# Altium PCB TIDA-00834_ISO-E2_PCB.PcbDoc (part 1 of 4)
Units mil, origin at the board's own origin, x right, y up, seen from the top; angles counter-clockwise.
Board outline 9055.12 x 4133.86 mil, 4 copper layers (Top Layer, GND, PWR, Bottom Layer), stack 61.92 mil thick; 647 components, 282 nets, 1430 pads, 409 vias.
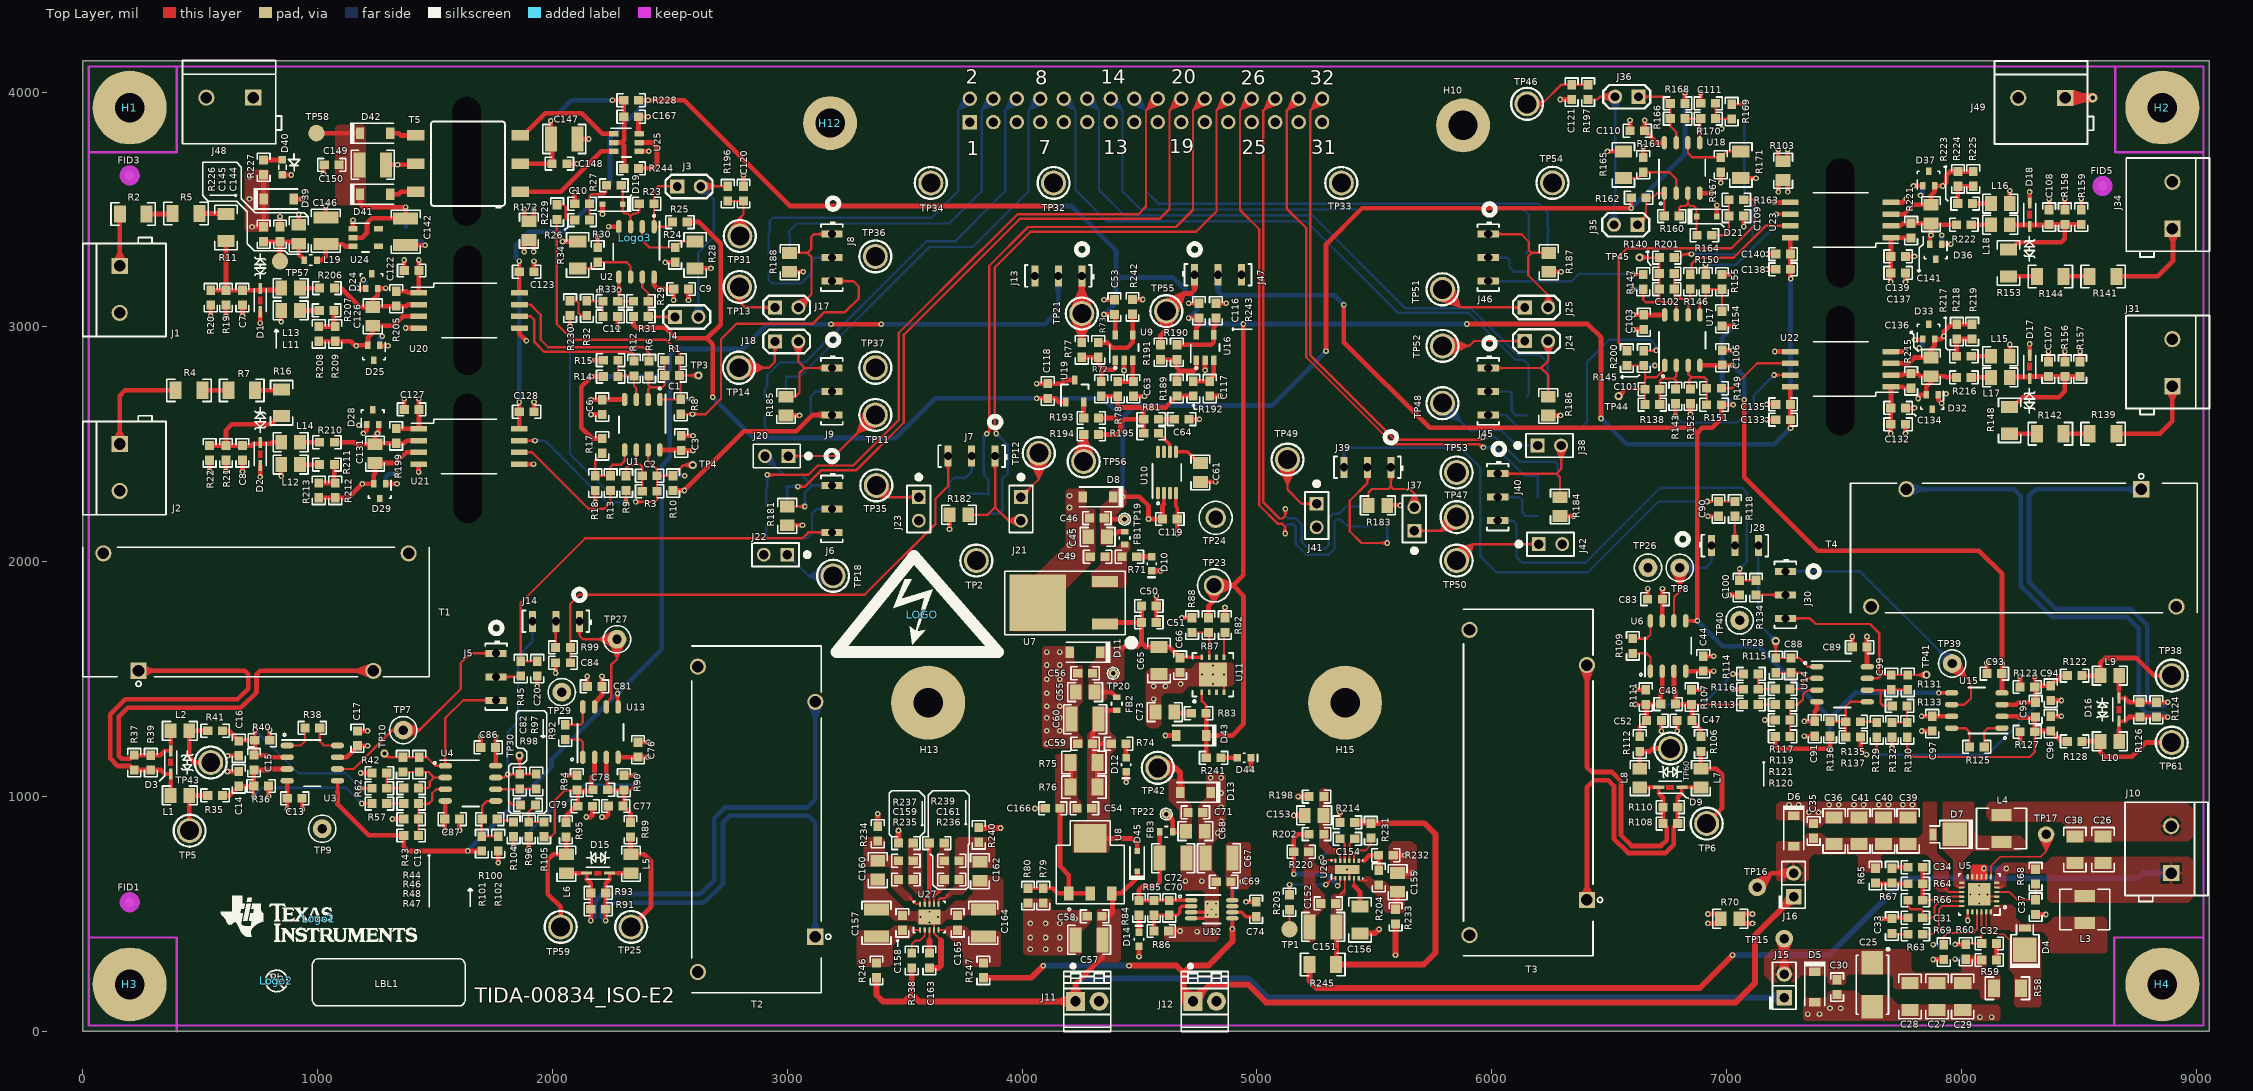
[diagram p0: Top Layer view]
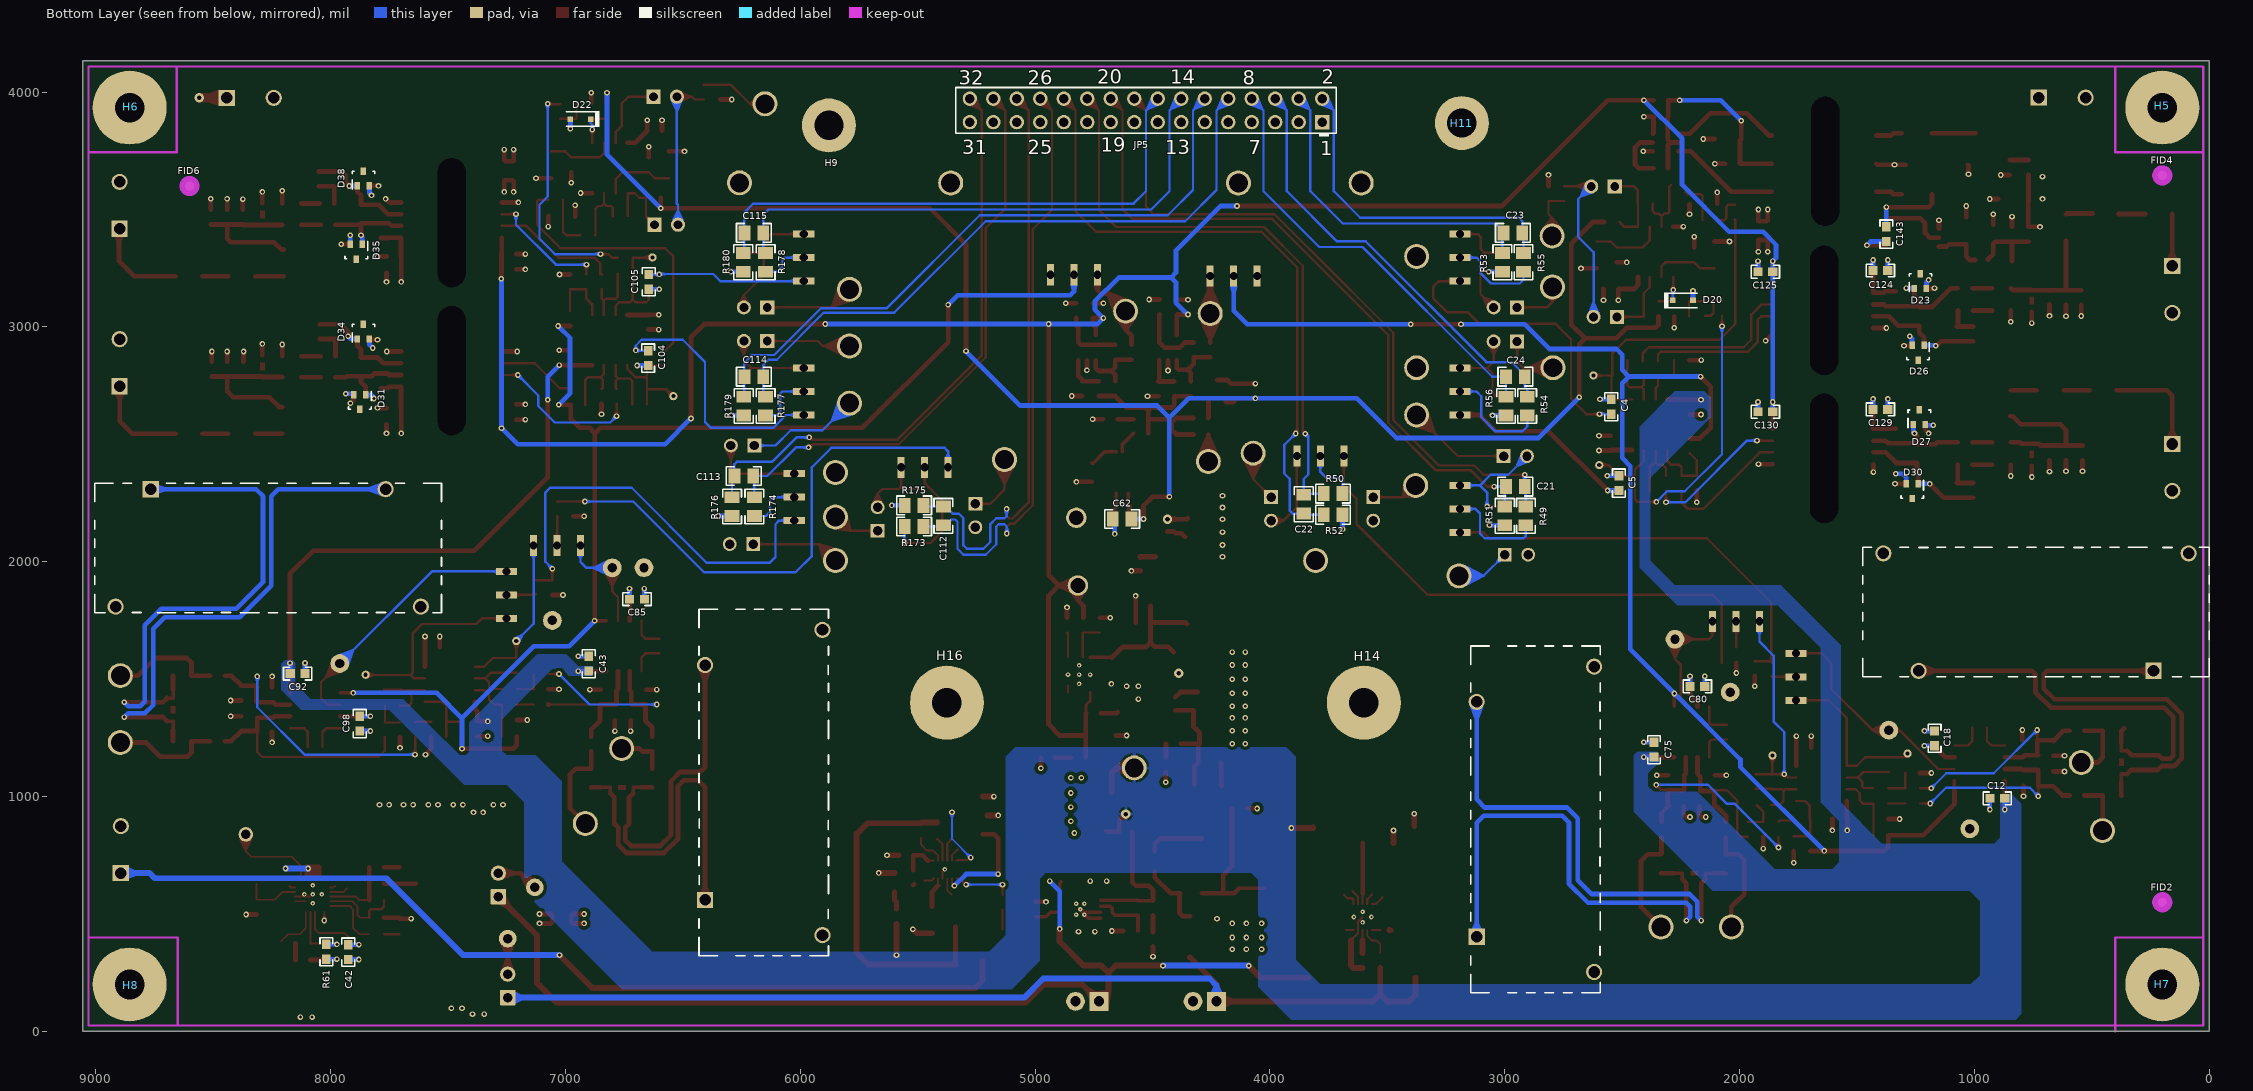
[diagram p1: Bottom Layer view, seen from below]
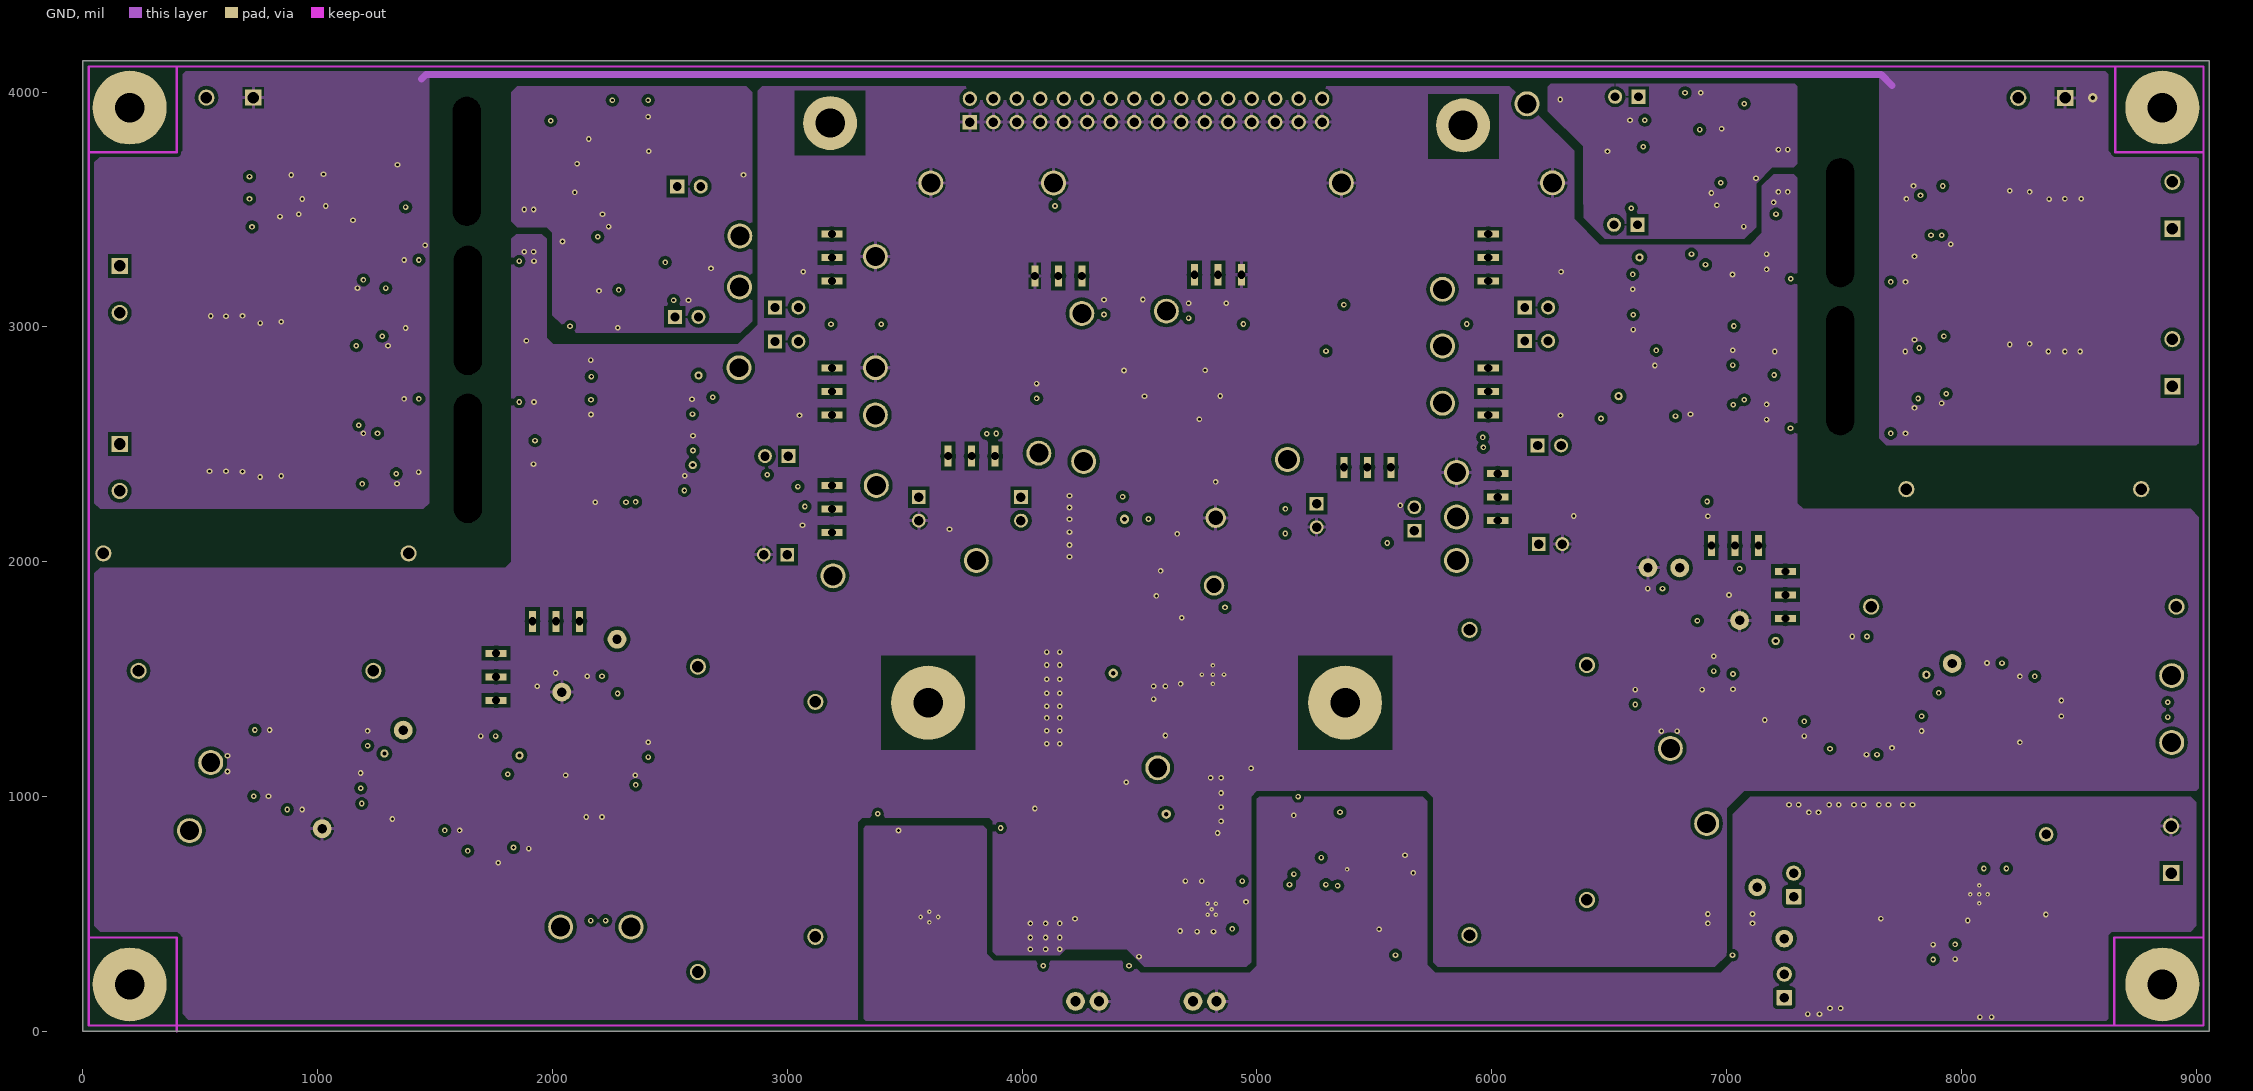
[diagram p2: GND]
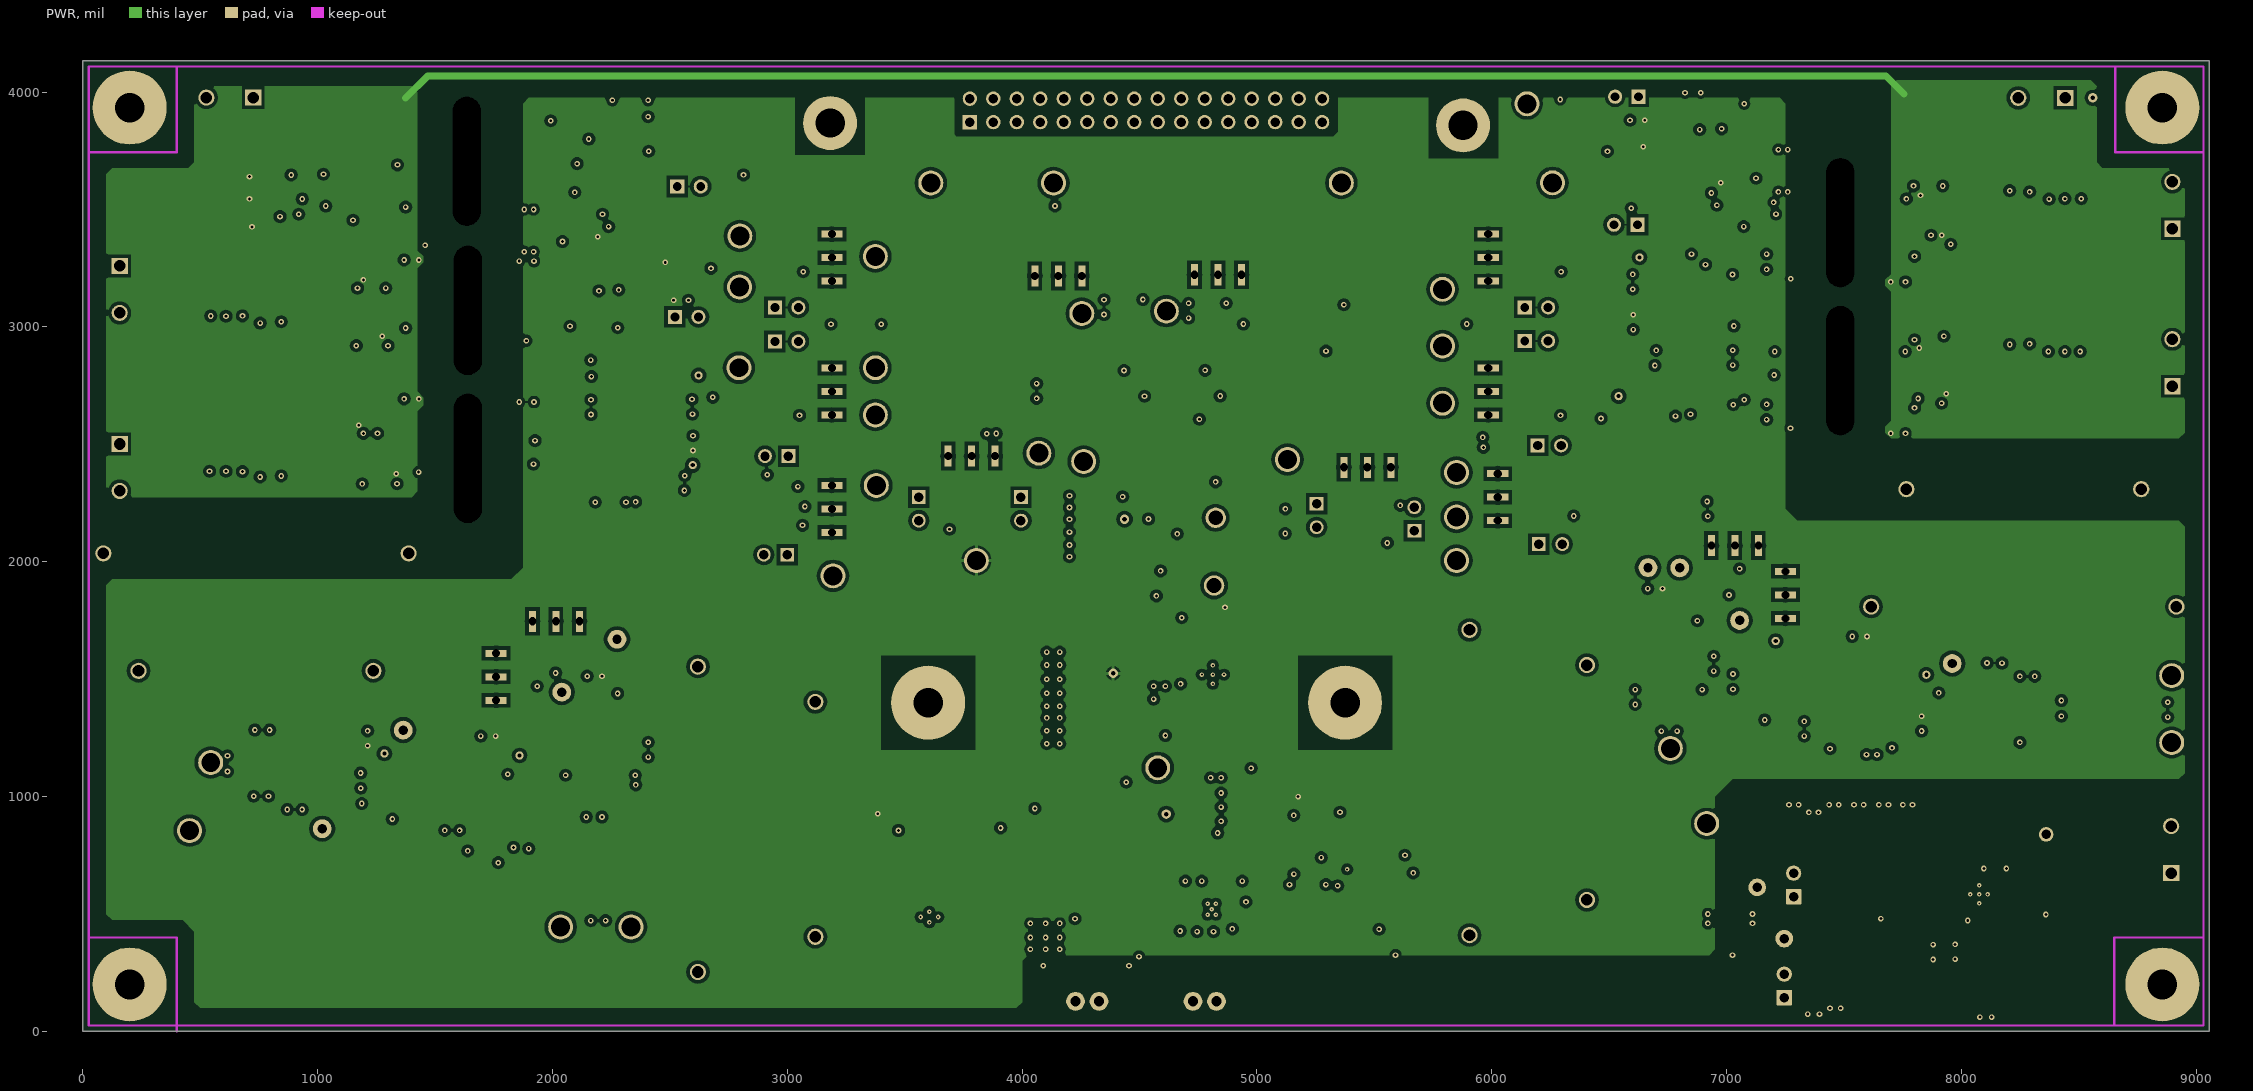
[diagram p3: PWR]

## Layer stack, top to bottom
Top Solder: solder mask 0.4, Solder Resist, Dk 4.3
Top Layer: signal copper 1.38
Dielectric1: prepreg 6.7, FR-4 High Tg, Dk 4.3
GND: signal copper 1.38
Dielectric 2: core 43, FR-4 High Tg, Dk 4.3
PWR: signal copper 1.38
Dielectric 3: prepreg 6.7, FR-4 High Tg, Dk 4.3
Bottom Layer: signal copper 1.38
Bottom Solder: solder mask 0.4, Solder Resist, Dk 4.3

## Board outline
0,0 0,4133.86 9055.12,4133.86 9055.12,0

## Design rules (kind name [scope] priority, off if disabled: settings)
AcuteAngle [All] p1: minimum=4.50000000000000E+0001 checktracksonly=FALSE
AssemblyTestPointUsage [All] p1: valid=2
Clearance Clearance_Keepouts [((IsTrack Or IsArc) And Not InPoly) And IsFree and IsKeepOut vs ((IsTrack Or IsArc) And Not InPoly) And IsFree and IsKeepOut] p1: gap=0
Clearance Clearance_Poly [InPolygon] p2: gap=25 except(8: SMDPad-Poly; 15: Track-Poly THPad-Poly Via-Poly; 20: Poly-Poly)
Clearance [All] p3: gap=7.87
ComponentClearance ComponentClearance_MountingHoles_FiducialMarks [InComponentClass('Mounting Holes') vs InComponentClass('FiducialMark')] p1: gap=50 collisioncheckmode=3 verticalgap=10 showdistances=FALSE
ComponentClearance ComponentClearance_Shunt [InComponentClass('Header') vs InComponentClass('Shunt')] p2: gap=0 collisioncheckmode=3 verticalgap=0 showdistances=FALSE
ComponentClearance ComponentClearance_Logo [InComponentClass('Logo')] p3: gap=50 collisioncheckmode=3 verticalgap=10 showdistances=FALSE
ComponentClearance ComponentClearance_ScrewToNut [(HasFootprint('NY PMS 440 0025 PH')) vs (HasFootprint('Keystone_1902C'))] p4: gap=5 collisioncheckmode=3 verticalgap=10 showdistances=FALSE
ComponentClearance ComponentClearance_MountingHoles [InComponentClass('Mounting Holes')] p5: gap=150 collisioncheckmode=3 verticalgap=100000 showdistances=FALSE
ComponentClearance ComponentClearance_SmallPassives [HasFootprint('0201*') or HasFootprint('0402*') or HasFootprint('0508') or HasFootprint('0603*') or HasFootprint('0612') or HasFootprint('0805*') or HasFootprint('0815*') or HasFootprint('0830*') or HasFootprint('1206*') or HasFootprint('1210*') or HasFootprint('1808*') or HasFootprint('1812*') or HasFootprint('1825*') or HasFootprint('2010*') or HasFootprint('2220*') or HasFootprint('2225*') or HasFootprint('2512*') or HasFootprint('2728*') or HasFootprint('3518*') vs HasFootprint('0201*') or HasFootprint('0402*') or HasFootprint('0508') or HasFootprint('0603*') or HasFootprint('0612') or HasFootprint('0805*') or HasFootprint('0815*') or HasFootprint('0830*') or HasFootprint('1206*') or HasFootprint('1210*') or HasFootprint('1808*') or HasFootprint('1812*') or HasFootprint('1825*') or HasFootprint('2010*') or HasFootprint('2220*') or HasFootprint('2225*') or HasFootprint('2512*') or HasFootprint('2728*') or HasFootprint('3518*')] p6: gap=14.96 collisioncheckmode=3 verticalgap=10 showdistances=FALSE
ComponentClearance ComponentClearance_THtoSMT [IsThruComponent vs IsSMTComponent] p7: gap=40 collisioncheckmode=3 verticalgap=30 showdistances=FALSE
ComponentClearance ComponentClearance_THtoTH [IsThruComponent vs IsThruComponent] p8: gap=30 collisioncheckmode=3 verticalgap=30 showdistances=FALSE
ComponentClearance [All] p9: gap=30 collisioncheckmode=3 verticalgap=10 showdistances=FALSE
DiffPairsRouting [All] p1: maxlimit=100 minlimit=10 mostfreqgap=10 toplayer_minwidth=15 toplayer_maxwidth=15 toplayer_prefwidth=15 midlayer1_minwidth=15 midlayer1_maxwidth=15 midlayer1_prefwidth=15 midlayer2_minwidth=15 midlayer2_maxwidth=15 midlayer2_prefwidth=15 bottomlayer_minwidth=15 bottomlayer_maxwidth=15 bottomlayer_prefwidth=15 maxuncoupledlength=1000
FabricationTestPointUsage TestPointUsage [All] p1: valid=2 allowmultiple=FALSE
FabricationTestpoint Testpoint [All] p1: side=3 testpointundercomponent=TRUE minsize=40 maxsize=100 preferedsize=60 minholesize=0 maxholesize=40 preferedholesize=32 testpointgrid=1 allowsidetop=TRUE allowsidebottom=TRUE usegrid=TRUE gridtolerance=0.01
FanoutControl Fanout_LCC [IsLCC] p1: bgadir=Out bgaviamode=Centered fanoutstyle=Auto fanoutdirection=Alternating viagrid=1 // Fanout_LCC (Default Rule)
FanoutControl Fanout_BGA [IsBGA] p2: bgadir=Out bgaviamode=Centered fanoutstyle=Auto fanoutdirection=Alternating viagrid=1 // Fanout_BGA (Default Rule)
FanoutControl Fanout_Default [All] p4: bgadir=Out bgaviamode=Centered fanoutstyle=Auto fanoutdirection=Alternating viagrid=1 // Fanout_Default (Default Rule)
FanoutControl Fanout_Small [(CompPinCount < 5)] p5: bgadir=Out bgaviamode=Centered fanoutstyle=Auto fanoutdirection=OutThenIn viagrid=1 // Fanout_Small (Default Rule)
HoleSize [All] p1: absolutevalues=TRUE maxlimit=251 minlimit=7.87 maxpercent=80.000 minpercent=20.000
MinimumAnnularRing MinimumAnnularRing_ThermalPadVias [IsVia and InAnyComponent] p1: minimumring=5.91
MinimumAnnularRing [All] p2: minimumring=6
MinimumSolderMaskSliver MinimumSolderMaskSliver_Logo [InComponentClass('Logo') vs InComponentClass('Logo')] p1: minsoldermaskwidth=0.7
MinimumSolderMaskSliver [All] p2: minsoldermaskwidth=3.94
PlaneConnect [All] p1: planeconnectstyle=Relief reliefexpansion=10 reliefentries=4 reliefconductorwidth=10 reliefairgap=10
PolygonConnect PolygonConnect_TH [IsThruPin] p1: connectstyle=Relief reliefconductorwidth=15 reliefentries=4 polygonreliefangle="90 Angle" airgapwidth=10
PolygonConnect [All] p2: connectstyle=Direct reliefconductorwidth=10 reliefentries=4 polygonreliefangle="90 Angle" airgapwidth=10
PolygonConnect PolygonConnect_via [Isvia] p3: connectstyle=Direct reliefconductorwidth=10 reliefentries=4 polygonreliefangle="90 Angle" airgapwidth=10
RoutingVias ThermalPadVias [IsVia and InAnyComponent] p1: holewidth=7.87 width=19.68 viastyle="Through Hole" minholewidth=7.87 minwidth=19.68 maxholewidth=12.99 maxwidth=23.62
RoutingVias [All] p2: holewidth=12 width=24 viastyle="Through Hole" minholewidth=7.87 minwidth=20 maxholewidth=20 maxwidth=40
SilkToSilkClearance SilkToSilkClearance_Pb-FreeLogo [(HasFootprint('Pb-Free_Overlay_Medium') OR HasFootprint('Pb-Free_Overlay_Small')) vs (HasFootprint('Pb-Free_Overlay_Medium') OR HasFootprint('Pb-Free_Overlay_Small'))] p1: silktosilkclearance=0
SilkToSilkClearance [All] p2: silktosilkclearance=0.75
SilkToSolderMaskClearance SilkToComponentPadClearance [IsPad and InAnycomponent] p1: minsilkscreentomaskgap=5 clearancetoexposedcopper=TRUE
SilkToSolderMaskClearance "Silk to Solder Mask Opening" [IsPad] p2: minsilkscreentomaskgap=4 clearancetoexposedcopper=TRUE
SolderMaskExpansion [All] p1: expansion=1.97
Width [All] p1: maxlimit=100 minlimit=6 preferedwidth=10 checkconnectedcopper=TRUE
16 further rules are at their usual default settings.

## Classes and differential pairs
component class "TIDA-00834E1_Pg7_ COMPARATOR": C9 C10 C11 C109 C110 C111 C120 C121 D19 D20 D21 D22 J3 J4 J35 J36 R23 R24 R25 R26 R27 R28 R29 R30 R31 R32 R33 R34 R103 R160 R161 R162 R163 R164 R165 R166 R167 R168 R169 R170 R171 R172 R196 R197 SH-J3 SH-J21 TP31 TP46 U2 U18
component class "TIDA-00834E1_Pg10_ ISOPOWER": C142 C143 C144 C145 C146 C147 C148 C149 C150 C167 D39 D40 D41 D42 L19 R226 R227 R228 R244 T5 TP57 TP58 U24 U25
component class TIDA-00834E1_Pg6_VOLTAGE2: C101 C102 C103 C104 C105 C106 C107 C108 C132 C133 C134 C135 C136 C137 C138 C139 C140 C141 D17 D18 D31 D32 D33 D34 D35 D36 D37 D38 J31 J34 J49 L15 L16 L17 L18 R138 R139 R140 R141 R142 R143 R144 R145 R146 R147 R148 R149 R150 R151 R152 R153 R154 R155 R156 R157 R158 R159 R200 R201 R215 R216 R217 R218 R219 R221 R222 R223 R224 R225 SH-J19 SH-J20 SH-J21 TP44 TP45 U17 U22 U23
component class TIDA-00834E1_Pg4_CT3_CT4: C43 C44 C47 C48 C52 C83 C85 C88 C89 C90 C91 C92 C93 C94 C95 C96 C97 C98 C99 C100 D9 D16 J28 J30 L7 L8 L9 L10 R106 R107 R108 R109 R110 R111 R112 R113 R114 R115 R116 R117 R118 R119 R120 R121 R122 R123 R124 R125 R126 R127 R128 R129 R130 R131 R132 R133 R134 R135 R136 R137 SH-J15 SH-J16 T3 T4 TP6 TP8 TP26 TP28 TP38 TP39 TP40 TP41 TP60 TP61 U6 U14 U15
component class TIDA-00834E1_Pg9_LDO: C45 C46 C49 C50 C51 C53 C54 C55 C56 C57 C58 C59 C60 C61 C62 C63 C64 C65 C66 C67 C68 C69 C70 C71 C72 C73 C74 C116 C117 C118 C119 C166 D8 D10 D11 D12 D13 D14 D43 D44 D45 FB1 FB2 FB3 J13 J47 R71 R72 R73 R74 R75 R76 R77 R78 R79 R80 R81 R82 R83 R84 R85 R86 R87 R88 R189 R190 R191 R192 R193 R194 R195 R241 R242 R243 SH-J4 TP2 TP19 TP20 TP21 TP22 TP23 TP24 TP42 TP55 TP56 U7 U8 U9 U10 U11 U12 U16 U19
component class "TIDA-00834E1_Pg8_Split Rail Converter": C25 C26 C27 C28 C29 C30 C31 C32 C33 C34 C35 C36 C37 C38 C39 C40 C41 C42 C151 C152 C153 C154 C155 C156 C157 C158 C159 C160 C161 C162 C163 C164 C165 D4 D5 D6 D7 J10 J11 J12 J15 J16 L3 L4 R58 R59 R60 R61 R63 R64 R65 R66 R67 R68 R69 R70 R198 R202 R203 R204 R214 R220 R231 R232 R233 R234 R235 R236 R237 R238 R239 R240 R245 R246 R247 TP1 TP15 TP16 TP17 U5 U26 U27
component class TIDA-00834E1_Pg11_Filters: C21 C22 C23 C24 C112 C113 C114 C115 J6 J7 J8 J9 J17 J18 J20 J21 J22 J23 J24 J25 J37 J38 J39 J40 J41 J42 J45 J46 JP5 R49 R50 R51 R52 R53 R54 R55 R56 R173 R174 R175 R176 R177 R178 R179 R180 R181 R182 R183 R184 R185 R186 R187 R188 SH-J3 TP11 TP12 TP13 TP14 TP18 TP32 TP33 TP34 TP35 TP36 TP37 TP47 TP48 TP49 TP50 TP51 TP52 TP53 TP54
component class Label: LBL1
component class AssemblyNote: ZZ1 ZZ2 ZZ3 ZZ4
component class FiducialMark: FID1 FID2 FID3 FID4 FID5 FID6
component class TIDA-00834E1_Pg12_EVM_Hardware: FID1 FID2 FID3 FID4 FID5 FID6 H1 H2 H3 H4 H5 H6 H7 H8 H9 H10 H11 h12 H13 H14 H15 H16 LBL1 LOGO Logo1 Logo2 Logo3 ZZ1 ZZ2 ZZ3 ZZ4
component class Logo: Logo1
component class "Mounting Holes": H1 H2 H3 H4 H13 H15
component class Header: J5 J6 J7 J8 J9 J13 J14 J15 J16 J20 J21 J22 J23 J28 J30 J37 J38 J39 J40 J41 J42 J45 J46 J47
component class TIDA-00834E1_Pg5_VOLTAGE: C1 C2 C3 C4 C5 C6 C7 C8 C122 C123 C124 C125 C126 C127 C128 C129 C130 C131 D1 D2 D23 D24 D25 D26 D27 D28 D29 D30 J1 J2 J48 L11 L12 L13 L14 R1 R2 R3 R4 R5 R6 R7 R8 R9 R10 R11 R12 R13 R14 R15 R16 R17 R18 R19 R20 R21 R22 R199 R205 R206 R207 R208 R209 R210 R211 R212 R213 R229 R230 TP3 TP4 U1 U20 U21
component class TIDA-00834E1_Pg3_CT1_CT2: C12 C13 C14 C15 C16 C17 C18 C19 C20 C75 C76 C77 C78 C79 C80 C81 C82 C84 C86 C87 D3 D15 J5 J14 L1 L2 L5 L6 R35 R36 R37 R38 R39 R40 R41 R42 R43 R44 R45 R46 R47 R48 R57 R62 R89 R90 R91 R92 R93 R94 R95 R96 R97 R98 R99 R100 R101 R102 R104 R105 SH-J1 SH-J2 T1 T2 TP5 TP7 TP9 TP10 TP25 TP27 TP29 TP30 TP43 TP59 U3 U4 U13

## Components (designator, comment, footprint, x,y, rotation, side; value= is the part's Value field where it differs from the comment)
C1 "06033C101KAT2A" 0603#1 2509.98,2792.72 r0 top
C2 "06033C101KAT2A" 0603#1 2413.5,2366.3 r0 top
C3 "06033C104JAT2A" 0603#1 2548.5,2505 r270 top
C4 "06033C101KAT2A" 0603#1 2546.08,2660 r90 bottom
C5 "06033C101KAT2A" 0603#1 2513.5,2335 r90 bottom
C6 "06033C104JAT2A" 0603#1 2212.38,2658.35 r90 top
C7 "C1608C0G1H102J" 0603#1 680,3125 r90 top
C8 "C1608C0G1H102J" 0603#1 680,2463.5 r90 top
C9 "06033C104JAT2A" 0603#1 2547.59,3161.22 r180 top
C10 "C1608C0G1E103J" 0603#1 2126.48,3524.57 r0 top
C11 "C1608C0G1E103J" 0603#1 2246.48,3044.57 r180 top
C12 "GRM188R61C105KA93D" 0603#1 902.6,992.52 r0 bottom
C13 "CGA3E2X8R1E104K080AA" 0603#1 902.6,992.52 r0 top
C14 "C0603X102K5RACTU" 0603#1 664.41,1075.04 r90 top
C15 "06031C103KAT2A" 0603#1 729.41,1145.04 r90 top
C16 "C0603X102K5RACTU" 0603#1 664.41,1205.04 r90 top
C17 "CGA3E2X8R1E104K080AA" 0603#1 1169.41,1248.17 r90 top
C18 "GRM188R61C105KA93D" 0603#1 1169.41,1248.17 r90 bottom
C19 "06033C101KAT2A" 0603#1 1433.09,1136.4 r90 top
C20 "06033C101KAT2A" 0603#1 1935,1545 r270 top
C21 "C0805C103K5RACTU" 0805_HV 2955,2320 r0 bottom
C22 "C0805C103K5RACTU" 0805_HV 3856,2245 r270 bottom
C23 "C0805C103K5RACTU" 0805_HV 2965,3400 r0 bottom
C24 "C0805C103K5RACTU" 0805_HV 2954.43,2788.05 r0 bottom
C25 "293D475X9025C2TE3" 6032-28 7620.12,198.86 r270 top
C26 "C3216X7R1E475M" 1206 8602.64,773.86 r90 top
C27 "C3216X7R1E475M" 1206 7895.12,148.86 r270 top
C28 "C3216X7R1E475M" 1206 7780.12,148.86 r270 top
C29 "C3216X7R1E475M" 1206 8005.12,148.86 r270 top
C30 "GRM188R70J103KA01D" 0603#1 7470.12,188.86 r270 top
C31 "C0603C224K9RACTU" 0603#1 7803.62,483.86 r0 top
C32 "C0603C100J5GACTU" 0603#1 8117.64,374.33 r180 top
C33 "GRM188R70J103KA01D" 0603#1 7703.62,448.86 r270 top
C34 "C0603C100J5GACTU" 0603#1 7803.62,698.86 r0 top
C35 "GRM188R70J103KA01D" 0603#1 7370.12,853.86 r90 top
C36 "C3216X7R1E475M" 1206 7457.64,854.33 r90 top
C37 "GRM188R61E105KA12D" 0603#1 8315.12,529.33 r270 top
C38 "C3216X7R1E475M" 1206 8482.64,773.86 r90 top
C39 "C3216X7R1E475M" 1206 7772.64,854.33 r90 top
C40 "C3216X7R1E475M" 1206 7667.64,854.33 r90 top
C41 "C3216X7R1E475M" 1206 7562.64,854.33 r90 top
C42 "GRM188R70J103KA01D" 0603#1 7923.94,338.03 r90 bottom
C43 "GRM188R61C105KA93D" 0603#1 6900.12,1565.71 r90 bottom
C44 "CGA3E2X8R1E104K080AA" 0603#1 6900.18,1565.71 r90 top
C45 "C2012X5R1H475M125AB" 0805_HV 4321.5,2106 r180 top
C46 "C0603C104K5RACTU" 0603#1 4318.35,2186 r180 top
C47 "C0603X102K5RACTU" 0603#1 6820.44,1323.86 r180 top
C48 "06031C103KAT2A" 0603#1 6750.44,1393.86 r180 top
C49 "CGA3E3X5R1H105K080AB" 0603#1 4321.5,2021 r180 top
C50 "CGA3E3X5R1H105K080AB" 0603#1 4540,1811.46 r0 top
C51 "C0603C104K5RACTU" 0603#1 4540,1741.46 r0 top
C52 "C0603X102K5RACTU" 0603#1 6690.44,1323.86 r180 top
C53 "C0603C104J4RACTU" 0603#1 4393,3084 r270 top
C54 "06031C103KAT2A" 0603#1 4265,950 r180 top
C55 "C2012X5R1H475M125AB" 0805_HV 4267.91,1445 r180 top
C56 "C0603C104K5RACTU" 0603#1 4267.91,1525 r180 top
C57 "GMK325AB7106MM-T" 1210 4285,390 r180 top
C58 "C0603C104K5RACTU" 0603#1 4308.5,490 r180 top
C59 "UMK107ABJ474KA-T" 0603#1 4267.91,1225 r180 top
C60 "GMK325AB7106MM-T" 1210 4267.91,1330 r180 top
C61 "C0805C105K8RACTU" 0805_HV 4759,2380 r270 top
C62 "C0805C105K8RACTU" 0805_HV 4629,2182 r0 bottom
C63 "C0603C104K8RACTU" 0603#1 4474,2736.25 r90 top
C64 "EMK107BBJ106MA-T" 0603#1 4679,2607 r0 top
C65 "885012208069" 1206 4582.4,1580 r270 top
C66 "06033C104JAT2A" 0603#1 4672.4,1560 r270 top
C67 "GMK325AB7106MM-T" 1210 4837.71,737.75 r0 top
C68 "C2012X5R1H475M125AB" 0805_HV 4737.71,852.75 r180 top
C69 "C0603C104K5RACTU" 0603#1 4857.71,637.75 r180 top
C70 "06031C103KAT2A" 0603#1 4626.44,525.75 r90 top
C71 "C0603C104K5RACTU" 0603#1 4737.71,932.75 r0 top
C72 "GMK325AB7106MM-T" 1210 4642.71,737.75 r180 top
C73 "C0805C225K8RACTU" 0805_HV 4607.4,1360 r180 top
C74 "06031C103KAT2A" 0603#1 4996.44,520.26 r270 top
C75 "GRM188R61C105KA93D" 0603#1 2364.41,1199.64 r90 bottom
C76 "CGA3E2X8R1E104K080AA" 0603#1 2364.41,1199.64 r90 top
C77 "C0603X102K5RACTU" 0603#1 2269.41,960.04 r180 top
C78 "06031C103KAT2A" 0603#1 2204.41,1029.09 r180 top
C79 "C0603X102K5RACTU" 0603#1 2139.41,959.09 r180 top
C80 "CGA3E2X8R1E104K080AA" 0603#1 2179.41,1469.09 r180 bottom
C81 "GRM188R61C105KA93D" 0603#1 2179.41,1469.09 r180 top
C82 "06033C101KAT2A" 0603#1 1860.94,1064.27 r90 top
C83 "CGA3E2X8R1E104K080AA" 0603#1 6694.8,1840.64 r180 top
C84 "06033C101KAT2A" 0603#1 2045,1570 r180 top
C85 "GRM188R61C105KA93D" 0603#1 6694.8,1840.58 r180 bottom
C86 "CGA3E2X8R1E104K080AA" 0603#1 1726.59,1209.27 r180 top
C87 "CGA3E2X8R1E104K080AA" 0603#1 1573.09,904.27 r0 top
C88 "06033C101KAT2A" 0603#1 7273.29,1558.33 r90 top
C89 "CGA3E2X8R1E104K080AA" 0603#1 7565.91,1636.65 r180 top
C90 "06033C101KAT2A" 0603#1 6965,2225 r270 top
C91 "CGA3E2X8R1E104K080AA" 0603#1 7375.12,1288.86 r270 top
C92 "GRM188R61C105KA93D" 0603#1 8140.12,1523.86 r180 bottom
C93 "CGA3E2X8R1E104K080AA" 0603#1 8140.12,1523.92 r180 top
C94 "C0603X102K5RACTU" 0603#1 8380.12,1440.67 r270 top
C95 "06031C103KAT2A" 0603#1 8315.12,1370.67 r270 top
C96 "C0603X102K5RACTU" 0603#1 8380.12,1310.67 r270 top
C97 "CGA3E2X8R1E104K080AA" 0603#1 7875.12,1310.67 r270 top
C98 "GRM188R61C105KA93D" 0603#1 7875.18,1310.67 r270 bottom
C99 "06033C101KAT2A" 0603#1 7701.14,1486.2 r90 top
C100 "06033C101KAT2A" 0603#1 7055,1890 r270 top
C101 "06033C101KAT2A" 0603#1 6683.36,2734.33 r180 top
C102 "06033C101KAT2A" 0603#1 6744.84,3160.74 r180 top
C103 "06033C104JAT2A" 0603#1 6647.26,3020 r90 top
C104 "06033C101KAT2A" 0603#1 6647.26,2867.04 r270 bottom
C105 "06033C101KAT2A" 0603#1 6644.84,3192.04 r270 bottom
C106 "06033C104JAT2A" 0603#1 6980.96,2868.7 r270 top
C107 "C1608C0G1H102J" 0603#1 8370,2820 r270 top
C108 "C1608C0G1H102J" 0603#1 8372.95,3467.48 r270 top
C109 "C1608C0G1E103J" 0603#1 7041.12,3471.84 r180 top
C110 "06033C104JAT2A" 0603#1 6620,3835.19 r0 top
C111 "C1608C0G1E103J" 0603#1 6921.12,3951.84 r0 top
C112 "C0805C103K5RACTU" 0805_HV 5390,2195 r90 bottom
C113 "C0805C103K5RACTU" 0805_HV 6240,2365.01 r0 bottom
C114 "C0805C103K5RACTU" 0805_HV 6197.38,2788.05 r0 bottom
C115 "C0805C103K5RACTU" 0805_HV 6197.38,3400 r0 bottom
C116 "C0603C104J4RACTU" 0603#1 4753,3069 r270 top
C117 "C0603C104K8RACTU" 0603#1 4799,2737 r90 top
C118 "C0603C104K5RACTU" 0603#1 4109,2727 r90 top
C119 "C0603C104K5RACTU" 0603#1 4629,2182 r0 top
C120 "C1608C0G1E103J" 0603#1 2813.52,3567.28 r270 top
C121 "C1608C0G1E103J" 0603#1 6340,4000 r90 top
C122 "" 0603#1 1400,3240 r180 top
C123 "" 0603#1 1890,3235 r180 top
C124 "GRM188R71C105KA12D" 0603#1 1400,3240 r0 bottom
C125 "GRM188R71C105KA12D" 0603#1 1890,3235 r0 bottom
C126 "08055A331KAT2A" 0805_HV 1235,3045 r270 top
C127 "" 0603#1 1400,2648.5 r180 top
C128 "" 0603#1 1890,2638.5 r180 top
C129 "GRM188R71C105KA12D" 0603#1 1400,2648.5 r0 bottom
C130 "GRM188R71C105KA12D" 0603#1 1890,2638.5 r0 bottom
C131 "08055A331KAT2A" 0805_HV 1244.61,2460.63 r270 top
C132 "" 0603#1 7730,2585 r0 top
C133 "" 0603#1 7240,2605 r0 top
C134 "GRM188R71C105KA12D" 0603#1 7730,2655 r180 top
C135 "GRM188R71C105KA12D" 0603#1 7240,2670 r180 top
C136 "08055A331KAT2A" 0805_HV 7870,2830 r90 top
C137 "" 0603#1 7730,3230 r0 top
C138 "" 0603#1 7240,3245 r0 top
C139 "GRM188R71C105KA12D" 0603#1 7730,3300 r180 top
C140 "GRM188R71C105KA12D" 0603#1 7240,3310 r180 top
C141 "08055A331KAT2A" 0805_HV 7870,3480 r90 top
C142 "" 1210 1375,3405 r90 top
C143 "" 0603#1 1375,3395 r270 bottom
C144 "" 0805_HV 920,3394.47 r270 top
C145 "" 0603#1 840,3394.47 r90 top
C146 "" 1210 1035,3409.47 r270 top
C147 "" 1210 2050,3800 r180 top
C148 "" 0603#1 2030,3695 r180 top
C149 "" 1210 1235,3690 r0 top
C150 "" 0603#1 1060,3690 r180 top
C151 "" 1210 5281.42,445 r0 top
C152 "GRM188R61E105KA12D" 0603#1 5303.5,545 r180 top
C153 "C0805C225K8RACTU" 0805_HV 5243.5,920 r180 top
C154 "GRM188R61E105KA12D" 0603#1 5385,820 r180 top
C155 "C0805C225K8RACTU" 0805_HV 5598.5,635 r90 top
C156 "C3216X7R1E475M" 1206 5438.5,475 r270 top
C157 "" 1210 3380,462.09 r270 top
C158 "GRM188R61E105KA12D" 0603#1 3490,462.09 r90 top
C159 "GRM188R70J103KA01D" 0603#1 3505,727.02 r0 top
C160 "C0805C225K8RACTU" 0805_HV 3385,687.09 r270 top
C161 "GRM188R70J103KA01D" 0603#1 3700,727.09 r180 top
C162 "C0805C225K8RACTU" 0805_HV 3820,682.09 r270 top
C163 "GRM188R70J103KA01D" 0603#1 3605,302.09 r270 top
C164 "" 1210 3835,462.09 r270 top
C165 "GRM188R61E105KA12D" 0603#1 3725,462.09 r90 top
C166 "C1608X5R1V335K080AC" 0603#1 4130,950 r180 top
C167 "" 0603#1 2335,3895 r180 top
D1 "PESD3V3L1BA" DIO_SOD323 755.48,3113.72 r270 top
D2 "PESD3V3L1BA" DIO_SOD323 755.45,2458.5 r270 top
D3 "PESD3V3L1BA" DIO_SOD323 374.41,1145.36 r90 top
D4 "MBRM120ET1G" POWERMITE 8270.12,393.86 r90 top
D5 "DZ2W15000L" SOD-123 7375.12,188.86 r270 top
D6 "DZ2W15000L" SOD-123 7285.12,853.86 r270 top
D7 "MBRM120ET1G" POWERMITE 7925.12,838.86 r180 top
D8 "MMSZ4685T1G" SOD-123 4323.35,2276 r180 top
D9 "PESD3V3L1BA" DIO_SOD323 6760,1040 r180 top
D10 "LG L29K-G2J1-24-Z" "LG L29K_GREEN" 4552.14,1991 r270 top
D11 "DZ2W15000L" SOD-123 4267.91,1615 r180 top
D12 "LG L29K-G2J1-24-Z" "LG L29K_GREEN" 4442.91,1135 r270 top
D13 "DZ2W15000L" SOD-123 4737.71,1017.75 r180 top
D14 "LG L29K-G2J1-24-Z" "LG L29K_GREEN" 4497.64,392.56 r90 top
D15 "PESD3V3L1BA" DIO_SOD323 2194.41,674.09 r180 top
D16 "PESD3V3L1BA" DIO_SOD323 8670.12,1370.35 r270 top
D17 "PESD3V3L1BA" DIO_SOD323 8290,2830 r90 top
D18 "PESD3V3L1BA" DIO_SOD323 8290,3477.48 r90 top
D19 "BAV19WS-7-F" SOD-323 2256.48,3522.72 r180 top
D20 "BAV19WS-7-F" SOD-323 2241.48,3112.72 r180 bottom
D21 "BAV19WS-7-F" SOD-323 6915,3470 r0 top
D22 "BAV19WS-7-F" SOD-323 6935,3885 r0 bottom
D23 "" SOT-323 1230,3195 r90 bottom
D24 "" SOT-323 1230,3195 r90 top
D25 "" SOT-323 1240,2890 r270 top
D26 "" SOT-323 1240,2890 r270 bottom
D27 "" SOT-323 1234.61,2615.63 r90 bottom
D28 "" SOT-323 1234.61,2615.63 r90 top
D29 "" SOT-323 1264.61,2300.63 r270 top
D30 "" SOT-323 1264.61,2300.63 r270 bottom
D31 "" SOT-323 7875,2680 r270 bottom
D32 "" SOT-323 7875,2680 r270 top
D33 "" SOT-323 7859.68,2980 r90 top
D34 "" SOT-323 7859.68,2980 r90 bottom
D35 "" SOT-323 7890,3320 r270 bottom
D36 "" SOT-323 7890,3320 r270 top
D37 "" SOT-323 7859.68,3631.82 r90 top
D38 "" SOT-323 7859.68,3631.82 r90 bottom
D39 "MMSZ5232B-7-F" SOD-123 835,3544.47 r0 top
D40 "" LED0603AA 850,3679.47 r90 top
D41 "B0520LW-7-F" SOD-123 1245,3565 r0 top
D42 "B0520LW-7-F" SOD-123 1245,3825 r0 top
D43 "MMSZ5232B-7-F" SOD-123 4720,1260 r180 top
D44 "LG L29K-G2J1-24-Z" "LG L29K_GREEN" 4945,1165 r0 top
D45 "BAS316,115" sod-323 4490,725 r90 top
FB1 "MMZ1608B102CTA00" MMZ1608_095 4436.5,2101 r90 top
FB2 "MMZ1608B102CTA00" MMZ1608_095 4402.91,1395 r90 top
FB3 "MMZ1608B102CTA00" MMZ1608_095 4613.18,850.13 r0 top
FID1 "Fiducial" Fiducial10-20 200,550 r0 top
FID2 "Fiducial" Fiducial10-20 200,550 r180 bottom
FID3 "Fiducial" Fiducial10-20 200,3645 r0 top
FID4 "Fiducial" Fiducial10-20 200,3645 r180 bottom
FID5 "Fiducial" Fiducial10-20 8600,3600 r0 top
FID6 "Fiducial" Fiducial10-20 8600,3600 r180 bottom
H1 "NY PMS 440 0025 PH" "NY PMS 440 0025 PH" 200,3933.86 r0 top locked
H2 "NY PMS 440 0025 PH" "NY PMS 440 0025 PH" 8855.12,3933.86 r0 top locked
H3 "NY PMS 440 0025 PH" "NY PMS 440 0025 PH" 200,200 r0 top locked
H4 "NY PMS 440 0025 PH" "NY PMS 440 0025 PH" 8855.12,200 r0 top locked
H5 "1902C" Keystone_1902C#1 200,3941.85 r180 bottom locked
H6 "1902C" Keystone_1902C#1 8851.05,3937.4 r180 bottom
H7 "1902C" Keystone_1902C#1 200,200 r180 bottom
H8 "1902C" Keystone_1902C#1 8850,196.85 r180 bottom
H9 "PMSSS 440 0025 PH" B_F_PMSSS4400025PH#1 537.4,7868.85 r180 bottom
H10 "1891" Keystone_1891 5877.4,3857.85 r0 top
H11 "PMSSS 440 0025 PH" B_F_PMSSS4400025PH#2 3182.4,3867.85 r180 bottom
H12 "1891" Keystone_1891 3182.4,3867.85 r0 top
H13 "NY PMS 440 0025 PH" "NY PMS 440 0025 PH" 3600,1400 r0 top
H14 "1902C" Keystone_1902C#2 3600,1400 r180 bottom
H15 "NY PMS 440 0025 PH" "NY PMS 440 0025 PH" 5375,1400 r0 top
H16 "1902C" Keystone_1902C#2 5375,1400 r180 bottom
J1 "ED120/2DS" CONN_ED120-2DS 157.48,3159.72 r180 top
J2 "ED120/2DS" CONN_ED120-2DS 157.48,2401.38 r180 top
J3 "JUMPER_2X100MIL" HDR100_1X2 2531.48,3597.72 r0 top
J4 "JUMPER_2X100MIL" HDR100_1X2 2521.48,3042.72 r0 top
J5 "5-146280-3" TE_5-146280-3 1760,1510 r270 top
J6 "5-146280-3" TE_5-146280-3 3190,2225 r270 top
J7 "5-146280-3" TE_5-146280-3 3785,2450 r180 top
J8 "5-146280-3" TE_5-146280-3 3190,3295 r270 top
J9 "5-146280-3" TE_5-146280-3 3190,2725 r270 top
J10 "ED120/2DS" CONN_ED120-2DS 8892.64,774.33 r0 top
J11 "CON-OSTVN02A150" CN2_MTB_P100_PD80_D1.1_S5.54X6.5_STACK 4277.4,127.95 r0 top
J12 "CON-OSTVN02A150" CN2_MTB_P100_PD80_D1.1_S5.54X6.5_STACK 4777.4,127.95 r0 top
J13 "5-146280-3" TE_5-146280-3 4154,3217 r180 top
J14 "5-146280-3" TE_5-146280-3 2015,1746.14 r180 top
J15 "5-146280-2" TSW-102-07-G-S 7245.12,193.86 r90 top
J16 "5-146280-2" TSW-102-07-G-S 7285.12,623.86 r90 top
J17 "JUMPER_2X100MIL" HDR100_1X2 2947,3083 r0 top
J18 "JUMPER_2X100MIL" HDR100_1X2 2947,2938 r0 top
J20 "5-146261-1" CONN_5-146261-1 2955,2450 r180 top
J21 "5-146261-1" CONN_5-146261-1 3995,2225.03 r270 top
J22 "5-146261-1" CONN_5-146261-1 2950,2030 r180 top
J23 "5-146261-1" CONN_5-146261-1 3560,2225.03 r270 top
J24 "JUMPER_2X100MIL" HDR100_1X2 6140,2940 r0 top
J25 "JUMPER_2X100MIL" HDR100_1X2 6140,3083 r0 top
J28 "5-146280-3" TE_5-146280-3 7035.12,2068.86 r0 top
J30 "5-146280-3" TE_5-146280-3 7250.12,1858.86 r270 top
J31 "ED120/2DS" CONN_ED120-2DS 8897.64,2847.48 r0 top
J34 "ED120/2DS" CONN_ED120-2DS 8897.95,3517.48 r0 top
J35 "JUMPER_2X100MIL" HDR100_1X2 6620,3435 r180 top
J36 "JUMPER_2X100MIL" HDR100_1X2 6625,3980 r180 top
J37 "5-146261-1" CONN_5-146261-1 5670,2181.85 r90 top
J38 "5-146261-1" CONN_5-146261-1 6245,2495.01 r0 top
J39 "5-146280-3" TE_5-146280-3 5470,2401.85 r180 top
J40 "5-146280-3" TE_5-146280-3 6025,2275.01 r270 top
J41 "5-146261-1" CONN_5-146261-1 5254,2197 r270 top
J42 "5-146261-1" CONN_5-146261-1 6250,2075 r0 top
J45 "5-146280-3" TE_5-146280-3 5985,2725 r270 top
J46 "5-146280-3" TE_5-146280-3 5985,3295 r270 top
J47 "5-146280-3" TE_5-146280-3 4834,3222 r0 top
J48 "ED120/2DS" CONN_ED120-2DS 626.38,3976.38 r90 top
J49 "ED120/2DS" CONN_ED120-2DS 8341.5,3975.24 r90 top
JP5 "5-534206-8" Samtec_SSW-116-01-x-D 4527.4,3921.85 r0 bottom
L1 "FBMJ2125HM210NT" 0805_HV 413.5,1005 r0 top
L2 "FBMJ2125HM210NT" 0805_HV 413.51,1280 r0 top
L3 "VLF504012MT-4R7M" IND_VLF504012 8525.12,518.86 r270 top
L4 "VLF504012MT-4R7M" IND_VLF504012 8170.12,863.86 r90 top
L5 "FBMJ2125HM210NT" 0805_HV 2334.41,714.09 r90 top
L6 "FBMJ2125HM210NT" 0805_HV 2059.41,714.09 r90 top
L7 "FBMJ2125HM210NT" 0805_HV 6890.12,1078.86 r90 top
L8 "FBMJ2125HM210NT" 0805_HV 6630.12,1078.86 r90 top
L9 "FBMJ2125HM210NT" 0805_HV 8631.5,1515 r180 top
L10 "FBMJ2125HM210NT" 0805_HV 8631.5,1235 r180 top
L11 "FBMJ2125HM210NT" 0805_HV 885,3070 r0 top
L12 "FBMJ2125HM210NT" 0805_HV 885,2413.5 r0 top
L13 "FBMJ2125HM210NT" 0805_HV 885,3165 r0 top
L14 "FBMJ2125HM210NT" 0805_HV 885,2508.5 r0 top
L15 "FBMJ2125HM210NT" 0805_HV 8165,2875 r180 top
L16 "FBMJ2125HM210NT" 0805_HV 8165,3525 r180 top
L17 "FBMJ2125HM210NT" 0805_HV 8165,2785 r180 top
L18 "FBMJ2125HM210NT" 0805_HV 8165,3435 r180 top
L19 "MMZ1608B102CTA00" MMZ1608_095 970,3284.47 r180 top
LBL1 "Size: 0.65\" x 0.20 \"" Label_650x200 1303,209.14 r0 top
LOGO "DANGER HIGH VOLTAGE" IEC_HighVoltage_Large 3575,1775 r0 top
Logo1 "Texas Instruments" TI_Stacked_Overlay_Small 1005,480 r0 top
Logo2 "Pb-Free Symbol" Pb-Free_Overlay_Small 825,215 r0 top
Logo3 "FCC disclaimer" FCC_disclaimer 2350,3380 r0 top
R1 "RC0603FR-0768KL" 0603#1 2509.98,2857.72 r180 top
R2 "RC1206FR-07330KL" 1206 215,3480.91 r180 top
R3 "RC0603FR-0768KL" 0603#1 2413.5,2300 r180 top
R4 "RC1206FR-07330KL" 1206 452.09,2730 r180 top
R5 "RC1206FR-07330KL" 1206 440,3482.91 r180 top
R6 "RC0603FR-0716KL" 0603#2 1776.63,1617.72 r90 top
R7 "RC1206FR-07330KL" 1206 677.09,2730 r180 top
R8 "CRCW0603100RFKEA" 0603#1 2546.08,2660 r270 top
R9 "RC0603FR-0716KL" 0603#1 2313.5,2334.68 r270 top
R10 "CRCW0603100RFKEA" 0603#1 2513.5,2335 r270 top
R11 "RC1206FR-07330KL" 1206 610,3422.91 r90 top
R12 "RC0603FR-0716KL" 0603#2 1712.38,1617.72 r90 top
R13 "RC0603FR-0716KL" 0603#1 2247.38,2334.68 r270 top
R14 "RC0603FR-0768KL" 0603#1 2247.38,2788.35 r0 top
R15 "CRCW0603130KFKEA" 0603#1 2247.38,2858.35 r0 top
R16 "RC1206FR-07330KL" 1206 847.09,2677.01 r90 top
R17 "RC0603FR-0768KL" 0603#1 2212.38,2493.35 r270 top
R18 "CRCW0603130KFKEA" 0603#1 2182.38,2334.68 r90 top
R19 "CRCW0603649RFKEA" 0603#1 610,3125 r90 top
R20 "CRCW0603649RFKEA" 0603#1 545,3125 r90 top
R21 "CRCW0603649RFKEA" 0603#1 610,2463.5 r90 top
R22 "CRCW0603649RFKEA" 0603#1 540,2463.5 r90 top
R23 "CRCW06031M00FKEA" 0603#1 2401.48,3524.57 r180 top
R24 "RC0603FR-07100KL" 0603#1 2522.59,3306.22 r270 top
R25 "CRCW060310K0FKEA" 0603#1 2542.59,3446.22 r0 top
R26 "CRCW0603100RFKEA" 0603#1 2126.48,3454.57 r0 top
R27 "CRCW060310K0FKEA" 0603#1 2261.48,3602.72 r0 top
R28 "CRCW12061K00FKEA" 1206 2607.59,3306.22 r90 top
R29 "CRCW06031M00FKEA" 0603#1 2376.48,3109.57 r180 top
R30 "RC0603FR-07100KL" 0603#1 2192.59,3306.22 r90 top
R31 "CRCW060310K0FKEA" 0603#1 2376.48,3044.57 r180 top
R32 "CRCW0603100RFKEA" 0603#1 2146.48,3079.57 r90 top
R33 "CRCW060310K0FKEA" 0603#1 2246.48,3109.57 r0 top
R34 "CRCW12061K00FKEA" 1206 2107.59,3306.22 r270 top
R35 "RT0603BRD07249RL" 0603#1 563.5,1005 r0 top
R36 "RC0603FR-07100KL" 0603#1 759.41,1045.04 r180 top
R37 "RC0603FR-07169RL" 0603#1 219.41,1145.04 r270 top
R38 "RG1608P-562-B-T5" 0603#1 977.6,1292.52 r0 top
R39 "CRCW060315R0FKEA" 0603#1 290,1145 r270 top
R40 "RC0603FR-07100KL" 0603#1 764.41,1240.04 r0 top
R41 "RT0603BRD07249RL" 0603#1 563.5,1280 r0 top
R42 "RC0603JR-070RL" 0603#1 1263.01,1100.28 r0 top
R43 "RG1608P-823-B-T5" 0603#1 1363.09,1136.4 r270 top
R44 "RC0603FR-078K2L" 0603#1 1398.09,1036.4 r180 top
R45 "CRCW0603100RFKEA" 0603#1 1865,1545 r90 top
R46 "RC0603FR-078K2L" 0603#1 1398.01,970.28 r180 top
R47 "RC0603FR-07100KL" 0603#1 1398.09,834.27 r0 top
R48 "RC0603FR-07100KL" 0603#1 1398.09,904.27 r0 top
R49 "CRCW08051K00FKEA" 0805_HV 2910,2195 r90 bottom
R50 "CRCW08051K00FKEA" 0805_HV 3731,2290 r0 bottom
R51 "CRCW08051K00FKEA" 0805_HV 3000,2195 r90 bottom
R52 "CRCW08051K00FKEA" 0805_HV 3731,2200 r0 bottom
R53 "CRCW08051K00FKEA" 0805_HV 2920,3275 r90 bottom
R54 "CRCW08051K00FKEA" 0805_HV 2904.43,2663.05 r90 bottom
R55 "CRCW08051K00FKEA" 0805_HV 3010,3275 r90 bottom
R56 "CRCW08051K00FKEA" 0805_HV 2994.43,2663.05 r90 bottom
R57 "RC0603JR-070RL" 0603#1 1263.01,970.28 r180 top
R58 "CRCW12060000Z0EA" 1206 8195.12,183.86 r180 top
R59 "CRCW06030000Z0EA" 0603#1 8117.64,304.33 r180 top
R60 "CRCW0603576KFKEA" 0603#1 8017.64,339.33 r270 top
R61 "RG1608P-4992-B-T5" 0603#1 8017.64,339.33 r270 bottom
R62 "RC0603JR-070RL" 0603#1 1263.01,1035.28 r180 top
R63 "CRCW06030000Z0EA" 0603#1 7803.62,413.86 r180 top
R64 "CRCW0603620KFKEA" 0603#1 7803.62,628.86 r180 top
R65 "CRCW06030000Z0EA" 0603#1 7633.62,663.86 r90 top
R66 "RG1608P-4992-B-T5" 0603#1 7803.62,558.86 r0 top
R67 "RG1608P-4992-B-T5" 0603#1 7703.62,663.86 r270 top
R68 "CR0603-J/-1R0ELF" 0603#1 8315.12,659.33 r270 top
R69 "CRCW06031K00JNEA" 0603#1 7923.94,338.03 r270 top
R70 "CRCW08050000Z0EA" 0805_HV 7015,480 r0 top
R71 "CRCW0603300RJNEA" 0603#1 4456.82,2021 r180 top
R72 "CRCW06030000Z0EA" 0603#1 4337.15,2736.25 r270 top
R73 "CRCW06030000Z0EA" 0603#1 4324,2902 r90 top
R74 "CRCW06033K90JNEA" 0603#1 4410.91,1225 r180 top
R75 "CRCW12062K00FKEA" 1206 4262.91,1145 r0 top
R76 "CRCW12062K00FKEA" 1206 4262.91,1040.32 r0 top
R77 "CRCW06030000Z0EA" 0603#1 4254,2902 r270 top
R78 "CRCW06030000Z0EA" 0603#1 4407.15,2736.25 r270 top
R79 "CRCW06038K45FKEA" 0603#1 4090,578.5 r90 top
R80 "CRCW0603100KFKEA" 0603#1 4025,578.5 r90 top
R81 "CRCW06030000Z0EA" 0603#1 4549,2607 r0 top
R82 "CRCW060310K0FKEA" 0603#1 4863.7,1730 r90 top
R83 "CRCW06030000Z0EA" 0603#1 4751.1,1355 r0 top
R84 "CRCW06033K90JNEA" 0603#1 4497.71,525.75 r90 top
R85 "CRCW06031M07FKEA" 0603#1 4561.44,525.75 r90 top
R86 "RC0603FR-07100KL" 0603#1 4592.71,427.75 r180 top
R87 "CRCW060331K6FKEA" 0603#1 4793.7,1730 r90 top
R88 "CRCW060310K0FKEA" 0603#1 4723.7,1730 r270 top
R89 "RT0603BRD07249RL" 0603#1 2332.35,859.09 r90 top
R90 "RC0603FR-07100KL" 0603#1 2304.41,1059.09 r270 top
R91 "RC0603FR-07169RL" 0603#1 2195,520 r0 top
R92 "RG1608P-562-B-T5" 0603#1 2054.41,1274.64 r90 top
R93 "CRCW060315R0FKEA" 0603#1 2195,590 r0 top
R94 "RC0603FR-07100KL" 0603#1 2104.41,1059.09 r90 top
R95 "RT0603BRD07249RL" 0603#1 2057.35,859.09 r90 top
R96 "RC0603JR-070RL" 0603#1 1899.41,860.04 r270 top
R97 "RG1608P-823-B-T5" 0603#1 1930.94,1064.27 r270 top
R98 "RC0603FR-078K2L" 0603#1 1895.94,964.27 r0 top
R99 "CRCW0603100RFKEA" 0603#1 2045,1635 r0 top
R100 "RC0603FR-078K2L" 0603#1 1733.09,904.27 r0 top
R101 "RC0603FR-07100KL" 0603#1 1699.41,800.1 r90 top
R102 "RC0603FR-07100KL" 0603#1 1769.41,800.1 r90 top
R103 "CRCW08050000Z0EA" 0805_HV 7240,3665 r90 top
R104 "RC0603JR-070RL" 0603#1 1834.41,860.1 r270 top
R105 "RC0603JR-070RL" 0603#1 1964.41,860.04 r270 top
R106 "RT0603BRD07249RL" 0603#1 6890.12,1223.86 r90 top
R107 "RC0603FR-07100KL" 0603#1 6850.44,1423.86 r270 top
R108 "RC0603FR-07169RL" 0603#3 6760,910 r0 top
R109 "RG1608P-562-B-T5" 0603#1 6600.43,1641.26 r90 top
R110 "CRCW060315R0FKEA" 0603#1 6760,955 r0 top
R111 "RC0603FR-07100KL" 0603#1 6655.44,1423.86 r90 top
R112 "RT0603BRD07249RL" 0603#1 6630.12,1223.86 r90 top
R113 "RC0603JR-070RL" 0603#1 7103.21,1392.2 r180 top
R114 "RC0603JR-070RL" 0603#1 7103.21,1522.2 r180 top
R115 "RG1608P-823-B-T5" 0603#1 7208.82,1558.86 r270 top
R116 "RC0603JR-070RL" 0603#1 7103.21,1457.2 r0 top
R117 "RC0603FR-078K2L" 0603#1 7238.29,1458.32 r180 top
R118 "CRCW0603100RFKEA" 0603#1 7035,2225 r90 top
R119 "RC0603FR-078K2L" 0603#1 7238.21,1391.65 r180 top
R120 "RC0603FR-07100KL" 0603#1 7238.29,1256.2 r0 top
R121 "RC0603FR-07100KL" 0603#1 7238.29,1326.2 r0 top
R122 "RT0603BRD07249RL" 0603#1 8481.5,1515 r180 top
R123 "RC0603FR-07100KL" 0603#1 8280.12,1466.65 r0 top
R124 "RC0603FR-07169RL" 0603#1 8830,1370 r90 top
R125 "RG1608P-562-B-T5" 0603#1 8065.12,1211.65 r180 top
R126 "CRCW060315R0FKEA" 0603#1 8760,1370 r90 top
R127 "RC0603FR-07100KL" 0603#1 8280.12,1275.67 r180 top
R128 "RT0603BRD07249RL" 0603#1 8481.5,1235 r180 top
R129 "RC0603JR-070RL" 0603#1 7638.82,1283.86 r270 top
R130 "RC0603JR-070RL" 0603#1 7768.82,1283.86 r270 top
R131 "RG1608P-823-B-T5" 0603#1 7771.14,1486.2 r270 top
R132 "RC0603JR-070RL" 0603#1 7703.82,1283.86 r270 top
R133 "RC0603FR-078K2L" 0603#1 7736.14,1386.2 r0 top
R134 "CRCW0603100RFKEA" 0603#1 7125,1890 r90 top
R135 "RC0603FR-078K2L" 0603#1 7538.82,1318.86 r0 top
R136 "RC0603FR-07100KL" 0603#1 7440.12,1288.86 r90 top
R137 "RC0603FR-07100KL" 0603#1 7538.82,1253.86 r180 top
R138 "RC0603FR-0768KL" 0603#1 6683.36,2669.33 r0 top
R139 "RC1206FR-07330KL" 1206 8602.91,2545 r0 top
R140 "RC0603FR-0768KL" 0603#1 6744.84,3227.04 r0 top
R141 "RC1206FR-07330KL" 1206 8602.91,3215 r0 top
R142 "RC1206FR-07330KL" 1206 8377.91,2545 r0 top
R143 "RC0603FR-0716KL" 0603#1 6781.71,2704.33 r270 top
R144 "RC1206FR-07330KL" 1206 8377.91,3215 r0 top
R145 "CRCW0603100RFKEA" 0603#1 6647.26,2867.04 r90 top
R146 "RC0603FR-0716KL" 0603#1 6844.84,3192.36 r90 top
R147 "CRCW0603100RFKEA" 0603#1 6644.84,3192.04 r90 top
R148 "RC1206FR-07330KL" 1206 8205,2602.09 r270 top
R149 "RC0603FR-0716KL" 0603#1 6945.96,2738.7 r0 top
R150 "RC0603FR-0716KL" 0603#1 6910.96,3192.36 r90 top
R151 "RC0603FR-0768KL" 0603#1 6945.96,2668.7 r180 top
R152 "CRCW0603130KFKEA" 0603#1 6845.96,2704.33 r90 top
R153 "RC1206FR-07330KL" 1206 8199.96,3272.52 r270 top
R154 "RC0603FR-0768KL" 0603#1 6980,3035 r90 top
R155 "CRCW0603130KFKEA" 0603#1 6980,3191.85 r270 top
R156 "CRCW0603649RFKEA" 0603#1 8440,2820 r270 top
R157 "CRCW0603649RFKEA" 0603#1 8505,2820 r270 top
R158 "CRCW0603649RFKEA" 0603#1 8440,3467.48 r270 top
R159 "CRCW0603649RFKEA" 0603#1 8510,3467.48 r270 top
R160 "CRCW06031M00FKEA" 0603#1 6766.12,3471.84 r0 top
R161 "RC0603FR-07100KL" 0603#1 6645,3690.19 r90 top
R162 "CRCW060310K0FKEA" 0603#1 6625,3550.19 r180 top
R163 "CRCW0603100RFKEA" 0603#1 7041.12,3541.68 r180 top
R164 "CRCW060310K0FKEA" 0603#1 6905,3390 r180 top
R165 "CRCW12061K00FKEA" 1206 6560,3690.19 r270 top
R166 "CRCW06031M00FKEA" 0603#1 6791.12,3886.84 r0 top
R167 "RC0603FR-07100KL" 0603#1 6975,3690.19 r270 top
R168 "CRCW060310K0FKEA" 0603#1 6791.12,3951.68 r0 top
R169 "CRCW0603100RFKEA" 0603#1 7021.12,3916.68 r270 top
R170 "CRCW060310K0FKEA" 0603#1 6921.12,3886.84 r180 top
R171 "CRCW12061K00FKEA" 1206 7060,3690.19 r90 top
R172 "CRCW08050000Z0EA" 0805_HV 1900,3410 r90 top
R173 "CRCW08051K00FKEA" 0805_HV 5515,2150 r180 bottom
R174 "CRCW08051K00FKEA" 0805_HV 6195,2235.01 r90 bottom
R175 "CRCW08051K00FKEA" 0805_HV 5515,2240 r180 bottom
R176 "CRCW08051K00FKEA" 0805_HV 6290,2235.01 r90 bottom
R177 "CRCW08051K00FKEA" 0805_HV 6147.38,2663.05 r90 bottom
R178 "CRCW08051K00FKEA" 0805_HV 6147.38,3275 r90 bottom
R179 "CRCW08051K00FKEA" 0805_HV 6240,2663.05 r90 bottom
R180 "CRCW08051K00FKEA" 0805_HV 6242.38,3275 r90 bottom
R181 "CRCW0805100KFKEA" 0805_HV 3000,2195 r90 top
R182 "CRCW0805100KFKEA" 0805_HV 3731,2200 r0 top
R183 "CRCW0805100KFKEA" 0805_HV 5515,2240 r180 top
R184 "CRCW0805100KFKEA" 0805_HV 6290,2235 r90 top
R185 "CRCW0805100KFKEA" 0805_HV 2994.43,2663.05 r90 top
R186 "CRCW0805100KFKEA" 0805_HV 6240,2663.05 r90 top
R187 "CRCW0805100KFKEA" 0805_HV 6242.38,3275 r90 top
R188 "CRCW0805100KFKEA" 0805_HV 3010,3275 r90 top
R189 "CRCW06030000Z0EA" 0603#1 4659,2737 r270 top
R190 "CRCW06030000Z0EA" 0603#1 4659,2892 r90 top
R191 "CRCW06030000Z0EA" 0603#1 4589,2892 r270 top
R192 "CRCW06030000Z0EA" 0603#1 4729,2737 r270 top
R193 "CRCW06030000Z0EA" 0603#1 4294,2612 r0 top
R194 "CRCW06030000Z0EA" 0603#1 4294,2542 r0 top
R195 "CRCW06030000Z0EA" 0603#1 4549,2547 r180 top
R196 "CRCW0603100RFKEA" 0603#1 2746.48,3567.72 r270 top
R197 "CRCW0603100RFKEA" 0603#1 6410,4000 r90 top
R198 "CRCW06030000Z0EA" 0603#1 5253.5,1000 r180 top
R199 "CRCW0603160KFKEA" 0603#1 1334.61,2535.63 r90 top
R200 "RC0603JR-070RL" 0603#1 6575,2867.04 r270 top
R201 "RC0603JR-070RL" 0603#1 6745,3295 r180 top
R202 "CRCW0603249KFKEA" 0603#1 5253.5,840 r0 top
R203 "CRCW060310K0FKEA" 0603#1 5138.5,550 r90 top
R204 "CRCW0603249KFKEA" 0603#1 5518.5,655 r270 top
R205 "CRCW0603160KFKEA" 0603#1 1335,3120 r90 top
R206 "RC0603FR-0712RL" 0603#1 1040,3165 r0 top
R207 "RC0603FR-0712RL" 0603#1 1038.5,3070 r0 top
R208 "CRCW0603649RFKEA" 0603#1 1005,2970 r90 top
R209 "CRCW0603649RFKEA" 0603#1 1075,2970 r90 top
R210 "RC0603FR-0712RL" 0603#1 1040,2508.5 r0 top
R211 "RC0603FR-0712RL" 0603#1 1040,2413.5 r0 top
R212 "CRCW0603649RFKEA" 0603#1 1075,2303.5 r90 top
R213 "CRCW0603649RFKEA" 0603#1 1005,2303.5 r90 top
R214 "CRCW06030000Z0EA" 0603#1 5385,890 r180 top
R215 "CRCW0603160KFKEA" 0603#1 7785,2770 r270 top
R216 "RC0603FR-0712RL" 0603#1 8010,2785 r180 top
R217 "RC0603FR-0712RL" 0603#1 8010,2875 r180 top
R218 "CRCW0603649RFKEA" 0603#1 7980,2980 r270 top
R219 "CRCW0603649RFKEA" 0603#1 8045,2980 r270 top
R220 "CRCW060375K0FKEA" 0603#1 5188.5,765 r180 top
R221 "CRCW0603160KFKEA" 0603#1 7785,3410 r270 top
R222 "RC0603FR-0712RL" 0603#1 8010,3435 r180 top
R223 "RC0603FR-0712RL" 0603#1 8015,3525 r180 top
R224 "CRCW0603649RFKEA" 0603#1 7985,3630 r270 top
R225 "CRCW0603649RFKEA" 0603#1 8050,3630 r270 top
R226 "CRCW06030000Z0EA" 0603#1 770,3394.47 r90 top
R227 "RC0603FR-07820RL" 0603#1 770,3679.47 r270 top
R228 "CRCW06030000Z0EA" 0603#1 2335,3965 r0 top
R229 "RC0603JR-070RL" 0603#1 2020,3489 r270 top
R230 "RC0603JR-070RL" 0603#1 2075,3080 r270 top
R231 "CRCW06030000Z0EA" 0603#1 5485,855 r270 top
R232 "CRCW060375K0FKEA" 0603#1 5548.5,750 r180 top
R233 "CRCW06030000Z0EA" 0603#1 5590,488.5 r270 top
R234 "CRCW06030000Z0EA" 0603#1 3385,842.09 r90 top
R235 "CRCW0603249KFKEA" 0603#1 3505,647.09 r180 top
R236 "CRCW0603249KFKEA" 0603#1 3700,647.02 r0 top
R237 "CRCW060375K0FKEA" 0603#1 3505,802.09 r0 top
R238 "CRCW06030000Z0EA" 0603#1 3530,302.09 r90 top
R239 "CRCW060375K0FKEA" 0603#1 3636.5,802.09 r0 top
R240 "CRCW06030000Z0EA" 0603#1 3815,837.09 r90 top
R241 "RC0603FR-07820RL" 0603#1 4815,1165 r180 top
R242 "CRCW06030000Z0EA" 0603#1 4470,3085 r90 top
R243 "CRCW06030000Z0EA" 0603#1 4825,3069 r90 top
R244 "CRCW06030000Z0EA" 0603#1 2335,3675 r0 top
R245 "CRCW12060000Z0EA" 1206 5280,285 r180 top
R246 "CRCW06030000Z0EA" 0603#1 3380,260 r90 top
R247 "CRCW06030000Z0EA" 0603#1 3835,260 r90 top
T1 "CR8350-2500-N" XFMR_CR8350-2500-N 737.6,1785.51 r90 top
T2 "CR8350-2500-N" XFMR_CR8350-2500-N 2869.41,903.19 r180 top
T3 "CR8350-2500-N" XFMR_CR8350-2500-N 6155,1060 r180 top
T4 "CR8350-2500-N" XFMR_CR8350-2500-N 8265.12,2058.86 r270 top
T5 "750313638" Wurth_750313638 1640,3695 r180 top
TP1 "Pogo Pad" PogoPad 5138.5,435 r90 top
TP2 "Suggest using a net name here" Keystone1573-2#1 3805,2005 r0 top
TP3 "TP-040_RND" TP_H045P075 2622.38,2793.34 r90 top
TP4 "TP-040_RND" TP_H045P075 2597.38,2411.49 r270 top
TP5 "Suggest using a net name here" Keystone1573-2#1 455,855 r180 top
TP6 "Suggest using a net name here" Keystone1573-2#1 6915,885 r0 top
TP7 "5002" Keystone5002 1364.41,1283.19 r180 top
TP8 "5002" Keystone5002 6800.12,1973.86 r0 top
TP9 "5001" Keystone5001 1019.41,863.19 r180 top
TP10 "TP-040_RND" TP_H045P075 1284.41,1183.19 r90 top
TP11 "Suggest using a net name here" Keystone1573-2#1 3375,2625 r0 top
TP12 "Suggest using a net name here" Keystone1573-2#1 4071,2462.15 r270 top
TP13 "Suggest using a net name here" Keystone1573-2#1 2797,3170 r0 top
TP14 "Suggest using a net name here" Keystone1573-2#1 2794,2826 r180 top
TP15 "TP-5001-BLACK" TH-40 7245.12,394.88 r90 top
TP16 "TP-5001-BLACK" TH-40 7130,613.74 r90 top
TP17 "TP-040_RND" TP-040_RND 8360.12,838.86 r0 top
TP18 "Suggest using a net name here" Keystone1573-2#1 3195,1940 r0 top
TP19 "TP1_PD40_D0.5_S50" TP1_PD40_D0.5_S50 4436,2181 r180 top
TP20 "TP1_PD40_D0.5_S50" TP1_PD40_D0.5_S50 4387.91,1525 r90 top
TP21 "Suggest using a net name here" Keystone1573-2#1 4254,3057 r90 top
TP22 "TP1_PD40_D0.5_S50" TP1_PD40_D0.5_S50 4613.57,925.33 r0 top
TP23 "+5V" Keystone5010 4817.4,1898.87 r270 top
TP24 "" Keystone5126 4824,2187 r270 top
TP25 "Suggest using a net name here" Keystone1573-2#1 2335,445 r90 top
TP26 "5001" Keystone5001 6665,1975 r0 top
TP27 "5002" Keystone5002 2275,1670 r270 top
TP28 "TP-040_RND" TP_H045P075 7208.82,1662.56 r90 top
TP29 "5001" Keystone5001 2040,1445 r270 top
TP30 "TP-040_RND" TP_H045P075 1860,1175 r270 top
TP31 "Suggest using a net name here" Keystone1573-2#1 2798,3387 r180 top
TP32 "Suggest using a net name here" Keystone1573-2#1 4134,3613 r90 top
TP33 "Suggest using a net name here" Keystone1573-2#1 5359,3613 r90 top
TP34 "Suggest using a net name here" Keystone1573-2#1 3611,3613 r90 top
TP35 "Suggest using a net name here" Keystone1573-2#1 3379,2325.03 r0 top
TP36 "Suggest using a net name here" Keystone1573-2#2 3205,2775 r0 top
TP37 "Suggest using a net name here" Keystone1573-2#1 3375,2826 r0 top
TP38 "Suggest using a net name here" Keystone1573-2#1 8895,1515 r0 top
TP39 "5002" Keystone5002 7960.12,1566.65 r0 top
TP40 "5001" Keystone5001 7055,1750 r0 top
TP41 "TP-040_RND" TP_H045P075 7850.12,1518.86 r90 top
TP42 "Suggest using a net name here" Keystone1573-2#1 4577.5,1122.5 r0 top
TP43 "Suggest using a net name here" Keystone1573-2#1 545,1145 r0 top
TP44 "TP-040_RND" TP_H045P075 6540,2705 r90 top
TP45 "TP-040_RND" TP_H045P075 6629,3296 r90 top
TP46 "Suggest using a net name here" Keystone1573-2#1 6150,3950 r0 top
TP47 "Suggest using a net name here" Keystone1573-2#1 5850,2190 r0 top
TP48 "Suggest using a net name here" Keystone1573-2#1 5790,2675 r90 top
TP49 "Suggest using a net name here" Keystone1573-2#1 5130,2435 r0 top
TP50 "Suggest using a net name here" Keystone1573-2#1 5850,2005 r90 top
TP51 "Suggest using a net name here" Keystone1573-2#1 5790,3160 r270 top
TP52 "Suggest using a net name here" Keystone1573-2#1 5790,2919 r270 top
TP53 "Suggest using a net name here" Keystone1573-2#1 5850,2380 r90 top
TP54 "Suggest using a net name here" Keystone1573-2#1 6258.28,3613.5 r90 top
TP55 "Suggest using a net name here" Keystone1573-2#1 4614,3067 r90 top
TP56 "Suggest using a net name here" Keystone1573-2#1 4262,2427 r0 top
TP57 "Pogo Pad" PogoPad 840,3279.47 r270 top
TP58 "Pogo Pad" PogoPad 995,3825 r90 top
TP59 "Suggest using a net name here" Keystone1573-2#1 2035,445 r0 top
TP60 "Suggest using a net name here" Keystone1573-2#1 6760,1205 r0 top
TP61 "Suggest using a net name here" Keystone1573-2#1 8895,1230 r0 top
U1 "OPA2188AID" D0008A_N 2382.38,2583.35 r270 top
U2 "LM2903DR" D0008A_N 2357.59,3319.57 r270 top
U3 "INA188ID" D0008A_N 977.6,1142.52 r0 top
U4 "OPA2188AID" D0008A_N 1651.29,1056.22 r0 top
U5 "TPS65131RGET" RGE0024B 8075.59,583.66 r180 top
U6 "INA188ID" D0008A_N 6750.43,1641.26 r90 top
U7 "TPS7A6533QKVURQ1" KVU_1 4210,1825 r90 top
U8 "TLV1117-XXCDCY" DCY 4290,690 r0 top
U9 "OPA322AIDBVR" DBV0005A_N 4434,2911.69 r90 top
U10 "REF5025AIDGKT" DGK0008A_N 4616.6,2380 r90 top
U11 "LP2951CSD" SDC08A 4812.4,1519.37 r90 top
U12 "TPS7A3001DGNR" DGN0008D_N 4807.4,520.26 r0 top
U13 "INA188ID" D0008A_N 2204.41,1274.64 r90 top
U14 "OPA2188AID" D0008A_N 7491.49,1478.15 r0 top
U15 "INA188ID" D0008A_N 8065.12,1366.65 r180 top
U16 "OPA322AIDBVR" DBV0005A_N 4779,2912 r90 top
U17 "OPA2188AID" D0008A_N 6810.96,2943.7 r90 top
U18 "LM2903DR" D0008A_N 6810,3676.85 r90 top
U19 "REF3025AIDBZR" DBZ0003A_N 4224,2727 r90 top
U20 "AMC1301DWVR" DWV0008A 1645,3070 r0 top
U21 "AMC1301DWVR" DWV0008A 1644.61,2490.63 r0 top
U22 "AMC1301DWVR" DWV0008A 7485,2820 r180 top
U23 "AMC1301DWVR" DWV0008A 7485,3455 r180 top
U24 "TLV70450DBVR" DBV0005A_N 1205,3380 r0 top
U25 "SN6505BDBVR" DBV0006A_N 2315,3785 r0 top
U26 "LM27762DSSR" DSS0012B 5383.66,689.84 r90 top
U27 "TPS7A3901DSC" DSC0010J 3605,487.09 r90 top
ZZ1 "This Assembly Note is for PCB labels only" AssemblyNoteLabel 169,4681 r0 top
ZZ2 "These assemblies are ESD sensitive, ESD precautions shall be observed." AssemblyNote 169,4572.11 r0 top
ZZ3 "These assemblies must be clean and free from flux and all contaminants. Use of no clean flux is not acceptable." AssemblyNote 169,4483.56 r0 top
ZZ4 "These assemblies must comply with workmanship standards IPC-A-610 Class 2, unless otherwise specified." AssemblyNote 169,4395 r0 top

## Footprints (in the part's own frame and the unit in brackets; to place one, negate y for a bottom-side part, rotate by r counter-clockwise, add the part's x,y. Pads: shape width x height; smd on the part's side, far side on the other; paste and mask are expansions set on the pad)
0603#1 [mm] "0603 from SM-752 data"
  rect 1x0.95 smd: 1(-0.8,0) 2(0.8,0)
  silkscreen extent -1.52,-0.69 1.52,0.69, body extent -0.87,-0.47 0.87,0.47, height 1
0603#2 [mm] "0603 from SM-752 data"
  rect 1x0.95 smd: 1(29.807,-16.129) 2(31.407,-16.129)
  silkscreen extent 29.08,-16.82 32.13,-15.44, body extent 29.73,-16.6 31.48,-15.65, height 1
0603#3 [mm] "0603 from SM-752 data"
  rect 1x0.95 smd: 1(-0.8,-0.635) 2(0.8,-0.635)
  silkscreen extent -1.52,-1.33 1.52,0.06, body extent -0.87,-1.11 0.87,-0.16, height 1
0805_HV [mil] "0805 with 30mil clearance between pads"
  rect 50x63 smd: 1(-40,0) 2(40,0)
  silkscreen extent -74,-40 74,40, body extent -43,-29 43,29, height 57
1206 [mm] "1206 from SM-752 data"
  rect 1.3x1.85 smd: 1(-1.45,0) 2(1.45,0)
  silkscreen extent -2.4,-1.21 2.4,1.21, body extent -1.7,-0.9 1.7,0.9, height 1.35
1210 [mm] "1210 from SM-752 data"
  rect 1.3x2.7 smd: 1(-1.45,0) 2(1.45,0)
  silkscreen extent -2.32,-1.57 2.32,1.57, body extent -1.7,-1.35 1.7,1.35, height 1.35
6032-28 [mm] "Medium Density IPC based on Vishay Sprague 293D datasheet."
  rect 2.55x2.3 smd: 1(-2.375,0) 2(2.375,0)
  silkscreen extent -3.96,-1.75 3.2,1.83, body extent -3.15,-1.75 3.15,1.75, height 2.8
AssemblyNote [mil] "Assembly Note"
AssemblyNoteLabel [mil] "Assembly Note for PCB Labels"
B_F_PMSSS4400025PH#1 [mil] "MACHINE SCREW PAN PHILLIPS 4-40"
  round 230 hole 125: 1(-5340,-4011)
  body extent -5450,-4120 -5231,-3901, height 79
B_F_PMSSS4400025PH#2 [mil] "MACHINE SCREW PAN PHILLIPS 4-40"
  round 230 hole 125: 1(0,0)
  body extent -109,-109 110,110, height 79
CN2_MTB_P100_PD80_D1.1_S5.54X6.5_STACK [mil]
  rect 80x80 / inner round 80 / far side rect 80x80 hole 44: 1(-50,0)
  round 80 hole 44: 2(50,0)
  silkscreen extent -100,-128 100,160
CONN_5-146261-1 [mm] "Sullins"
  rect 1.5x1.5 hole 1.02: 1(-1.27,0)
  round 1.5 hole 1.02: 2(1.27,0)
  silkscreen extent -3.68,-1.27 2.54,1.27, body extent -2.51,-1.27 2.51,1.27, height 10.87
CONN_ED120-2DS [mm] "ONSHORE"
  rect 1.75x1.75 hole 1.25: 1(0,-2.54)
  round 1.75 hole 1.25: 2(0,2.54)
  silkscreen extent -5,-5.6 4,5.12, body extent -5,-5.6 4.15,5.12, height 13.1
D0008A_N [mm] "SOIC, 8-Leads, Body 4.9x3.9mm, Pitch 1.27mm, IPC Medium Density"
  oval 1.45x0.6 smd: 1(-2.725,1.905) 2(-2.725,0.635) 3(-2.725,-0.635) 4(-2.725,-1.905) 5(2.725,-1.905) 6(2.725,-0.635) 7(2.725,0.635) 8(2.725,1.905)
  silkscreen extent -3.3,-2.5 0.9,2.5, body extent -3,-2.45 3,2.45, height 1.63
DBV0005A_N [mm] "SOT23, 5-Leads, Body 2.9x1.6mm, Pitch 0.95mm, Lead Span 2.8mm, IPC Medium Density"
  rrect17% 1x0.6 smd: 1(-1.375,0.95) 2(-1.375,0) 3(-1.375,-0.95) 4(1.375,-0.95) 5(1.375,0.95)
  silkscreen extent -1.63,-1.55 0.38,1.55, body extent -1.42,-1.46 1.42,1.46, height 1.09
DBV0006A_N [mm] "SOT23, 6-Leads, Body 2.9x1.6mm, Pitch 0.95mm, Lead Span 2.8mm, IPC Medium Density"
  rrect17% 1x0.6 smd: 1(-1.375,0.95) 2(-1.375,0) 3(-1.375,-0.95) 4(1.375,-0.95) 5(1.375,0) 6(1.375,0.95)
  silkscreen extent -1.68,-1.55 0.5,1.55, body extent -1.42,-1.46 1.42,1.46, height 1.12
DBZ0003A_N [mm] "SOT23, 3-Leads, Body 2.9x1.3mm, Pitch 0.95mm, Lead Span 2.4mm, IPC Medium Density"
  rrect17% 1x0.6 smd: 1(-1.2,0.95) 2(-1.2,-0.95) 3(1.2,0)
  silkscreen extent -1.65,-1.5 0.7,1.5, body extent -1.26,-1.46 1.26,1.46, height 0.98
DCY [mil]
  rect 40x60 smd: 1(-91,-102.2) 2(0,-102.2) 3(91,-102.2)
  rect 140x120 smd: 4(0,132.3)
DGK0008A_N [mm] "TSOP, 8-Leads, Body 3x3mm, Pitch 0.65mm, IPC Medium Density"
  oval 1.35x0.45 smd: 1(-2.225,0.975) 2(-2.225,0.325) 3(-2.225,-0.325) 4(-2.225,-0.975) 5(2.225,-0.975) 6(2.225,-0.325) 7(2.225,0.325) 8(2.225,0.975)
  silkscreen extent -2.75,-1.55 0.95,1.55, body extent -2.45,-1.5 2.45,1.5, height 0.96
DGN0008D_N [mm] "TSOP, 8-Leads, Body 3x3mm, Pitch 0.65mm, Thermal Pad 1.89x1.57mm, IPC Medium Density"
  rrect100% 1.35x0.45 smd: 1(-2.225,0.975) 2(-2.225,0.325) 3(-2.225,-0.325) 4(-2.225,-0.975) 5(2.225,-0.975) 6(2.225,-0.325) 7(2.225,0.325) 8(2.225,0.975)
  rrect6% 1.57x1.89 smd: 9(0,0)
  silkscreen extent -2.73,-1.55 0.95,1.55, body extent -2.46,-1.5 2.46,1.5, height 1.1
